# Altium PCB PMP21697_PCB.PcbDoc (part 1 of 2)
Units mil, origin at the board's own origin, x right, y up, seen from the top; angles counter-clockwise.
Board outline 4950 x 3450 mil, 6 copper layers (Top Layer, Signal Layer 1, Signal Layer 2, Signal Layer 3, Signal Layer 4, Bottom Layer), stack 60.502 mil thick; 163 components, 60 nets, 332 pads, 953 vias.
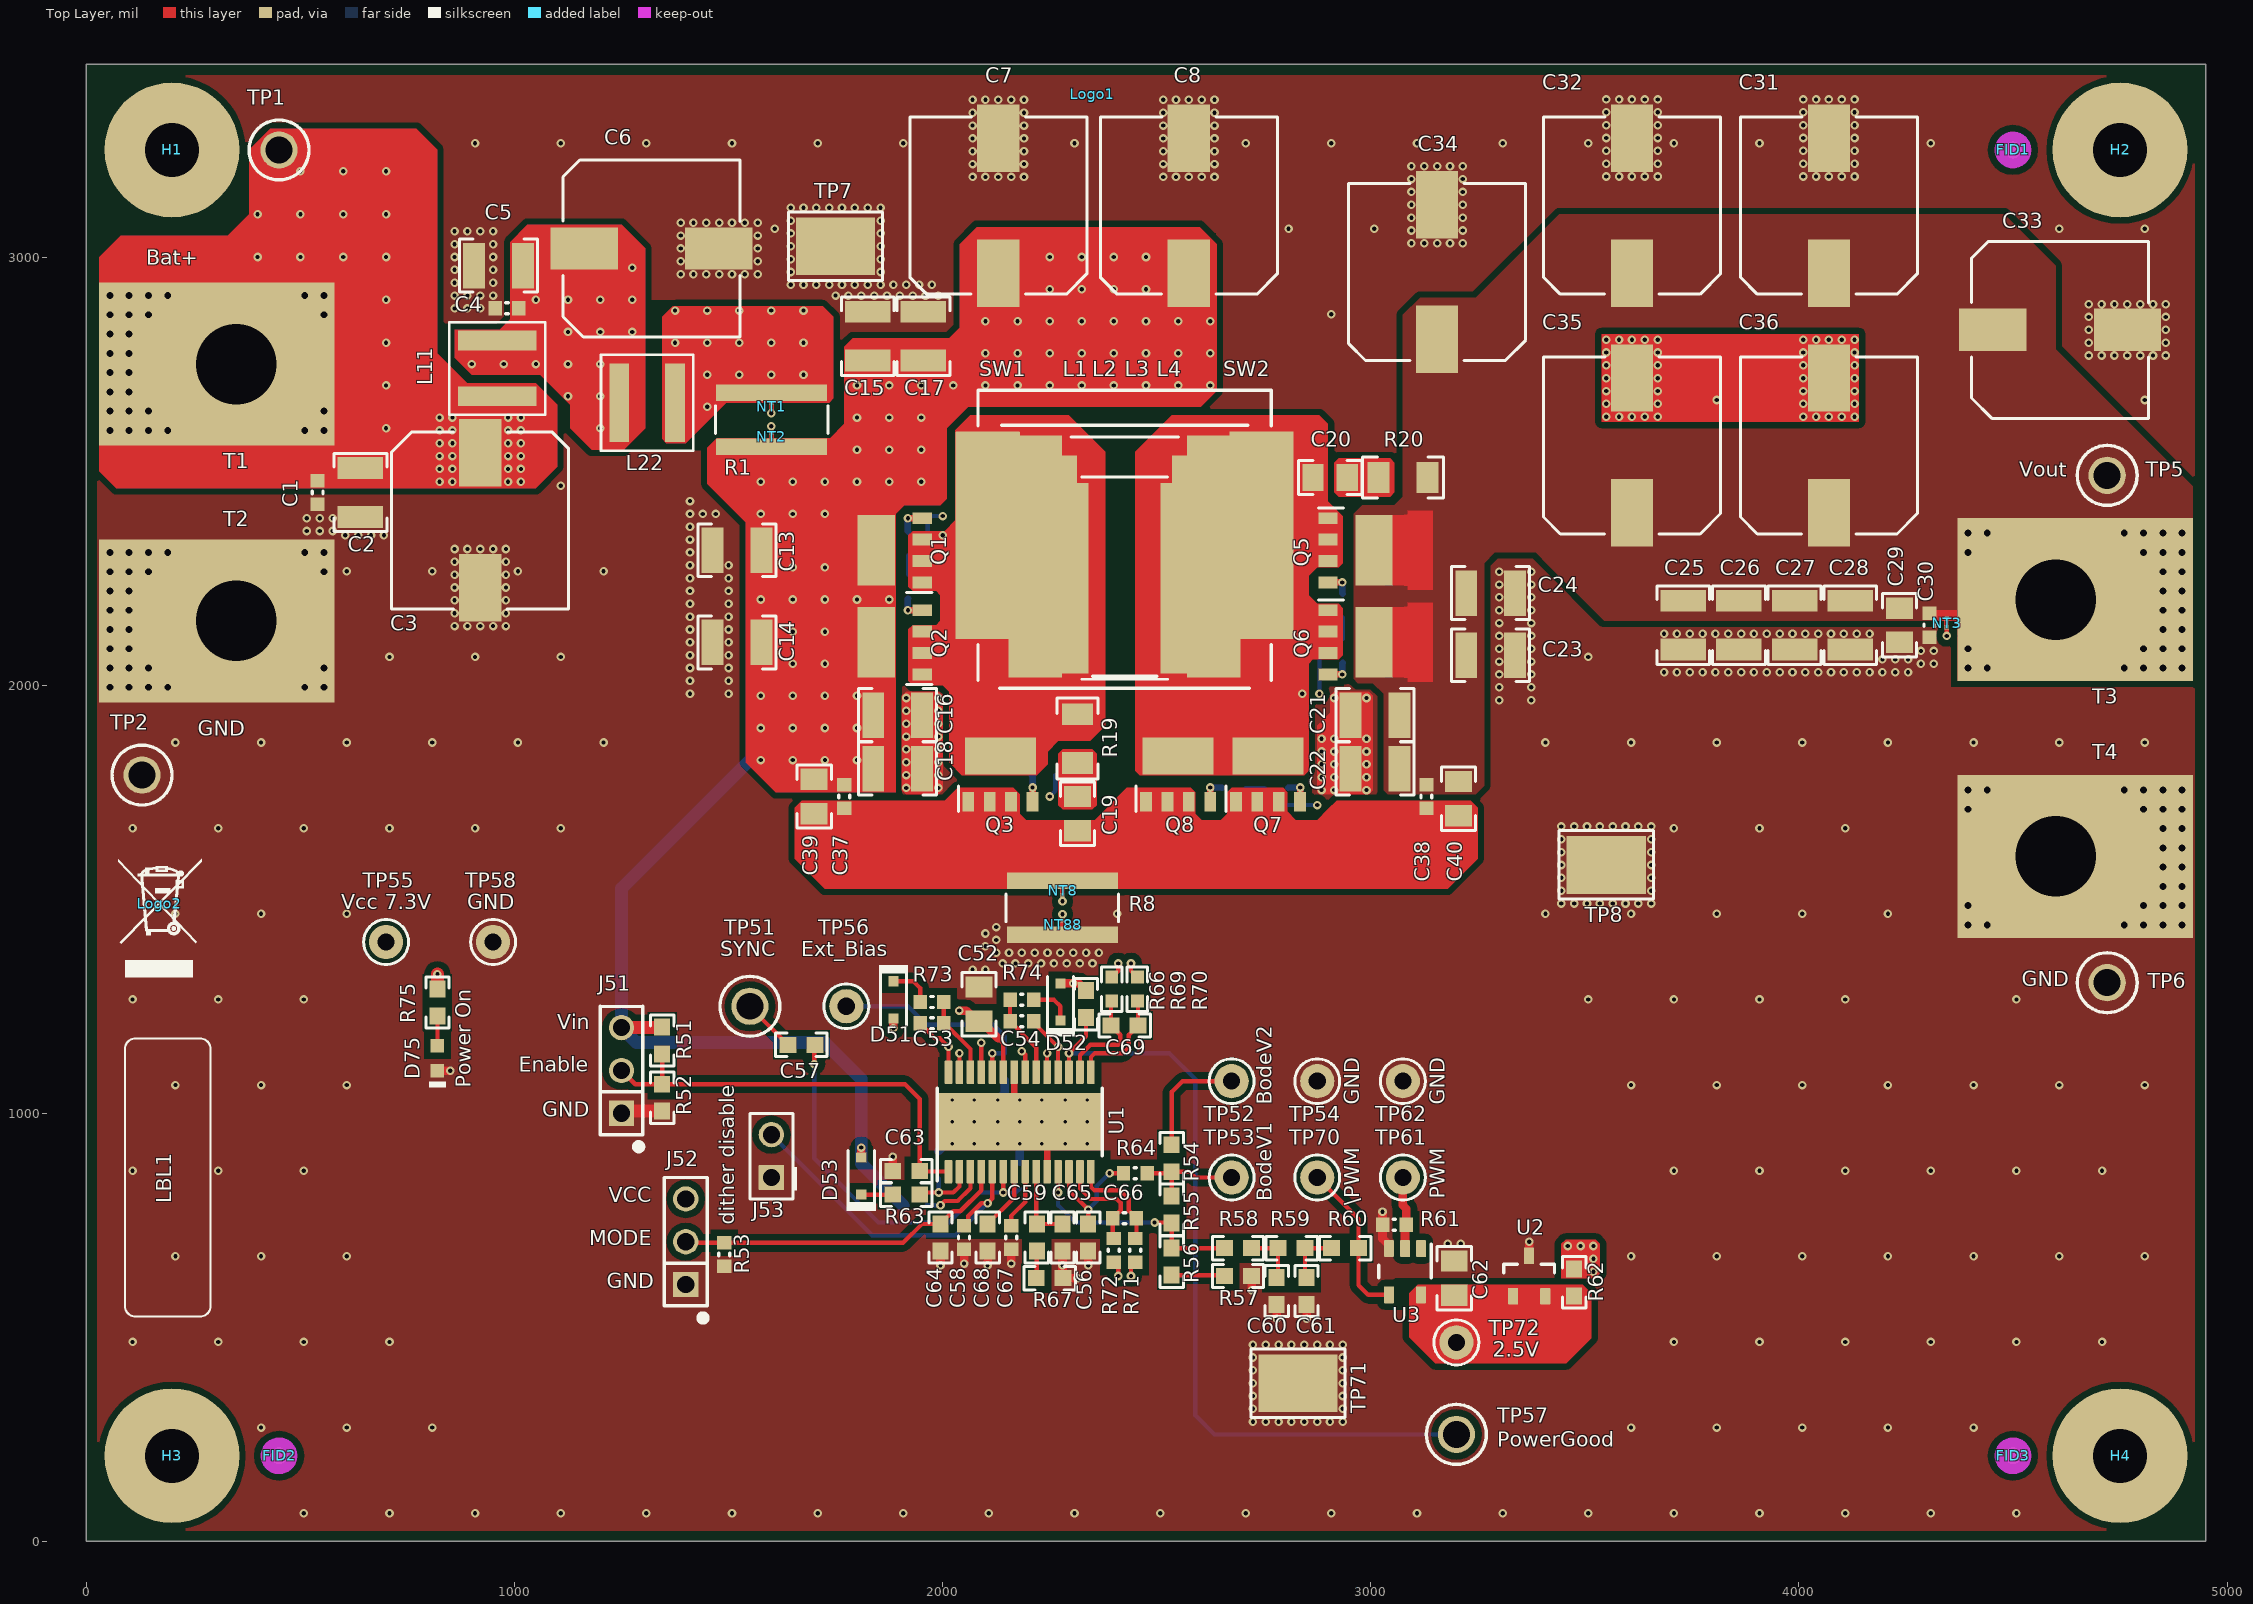
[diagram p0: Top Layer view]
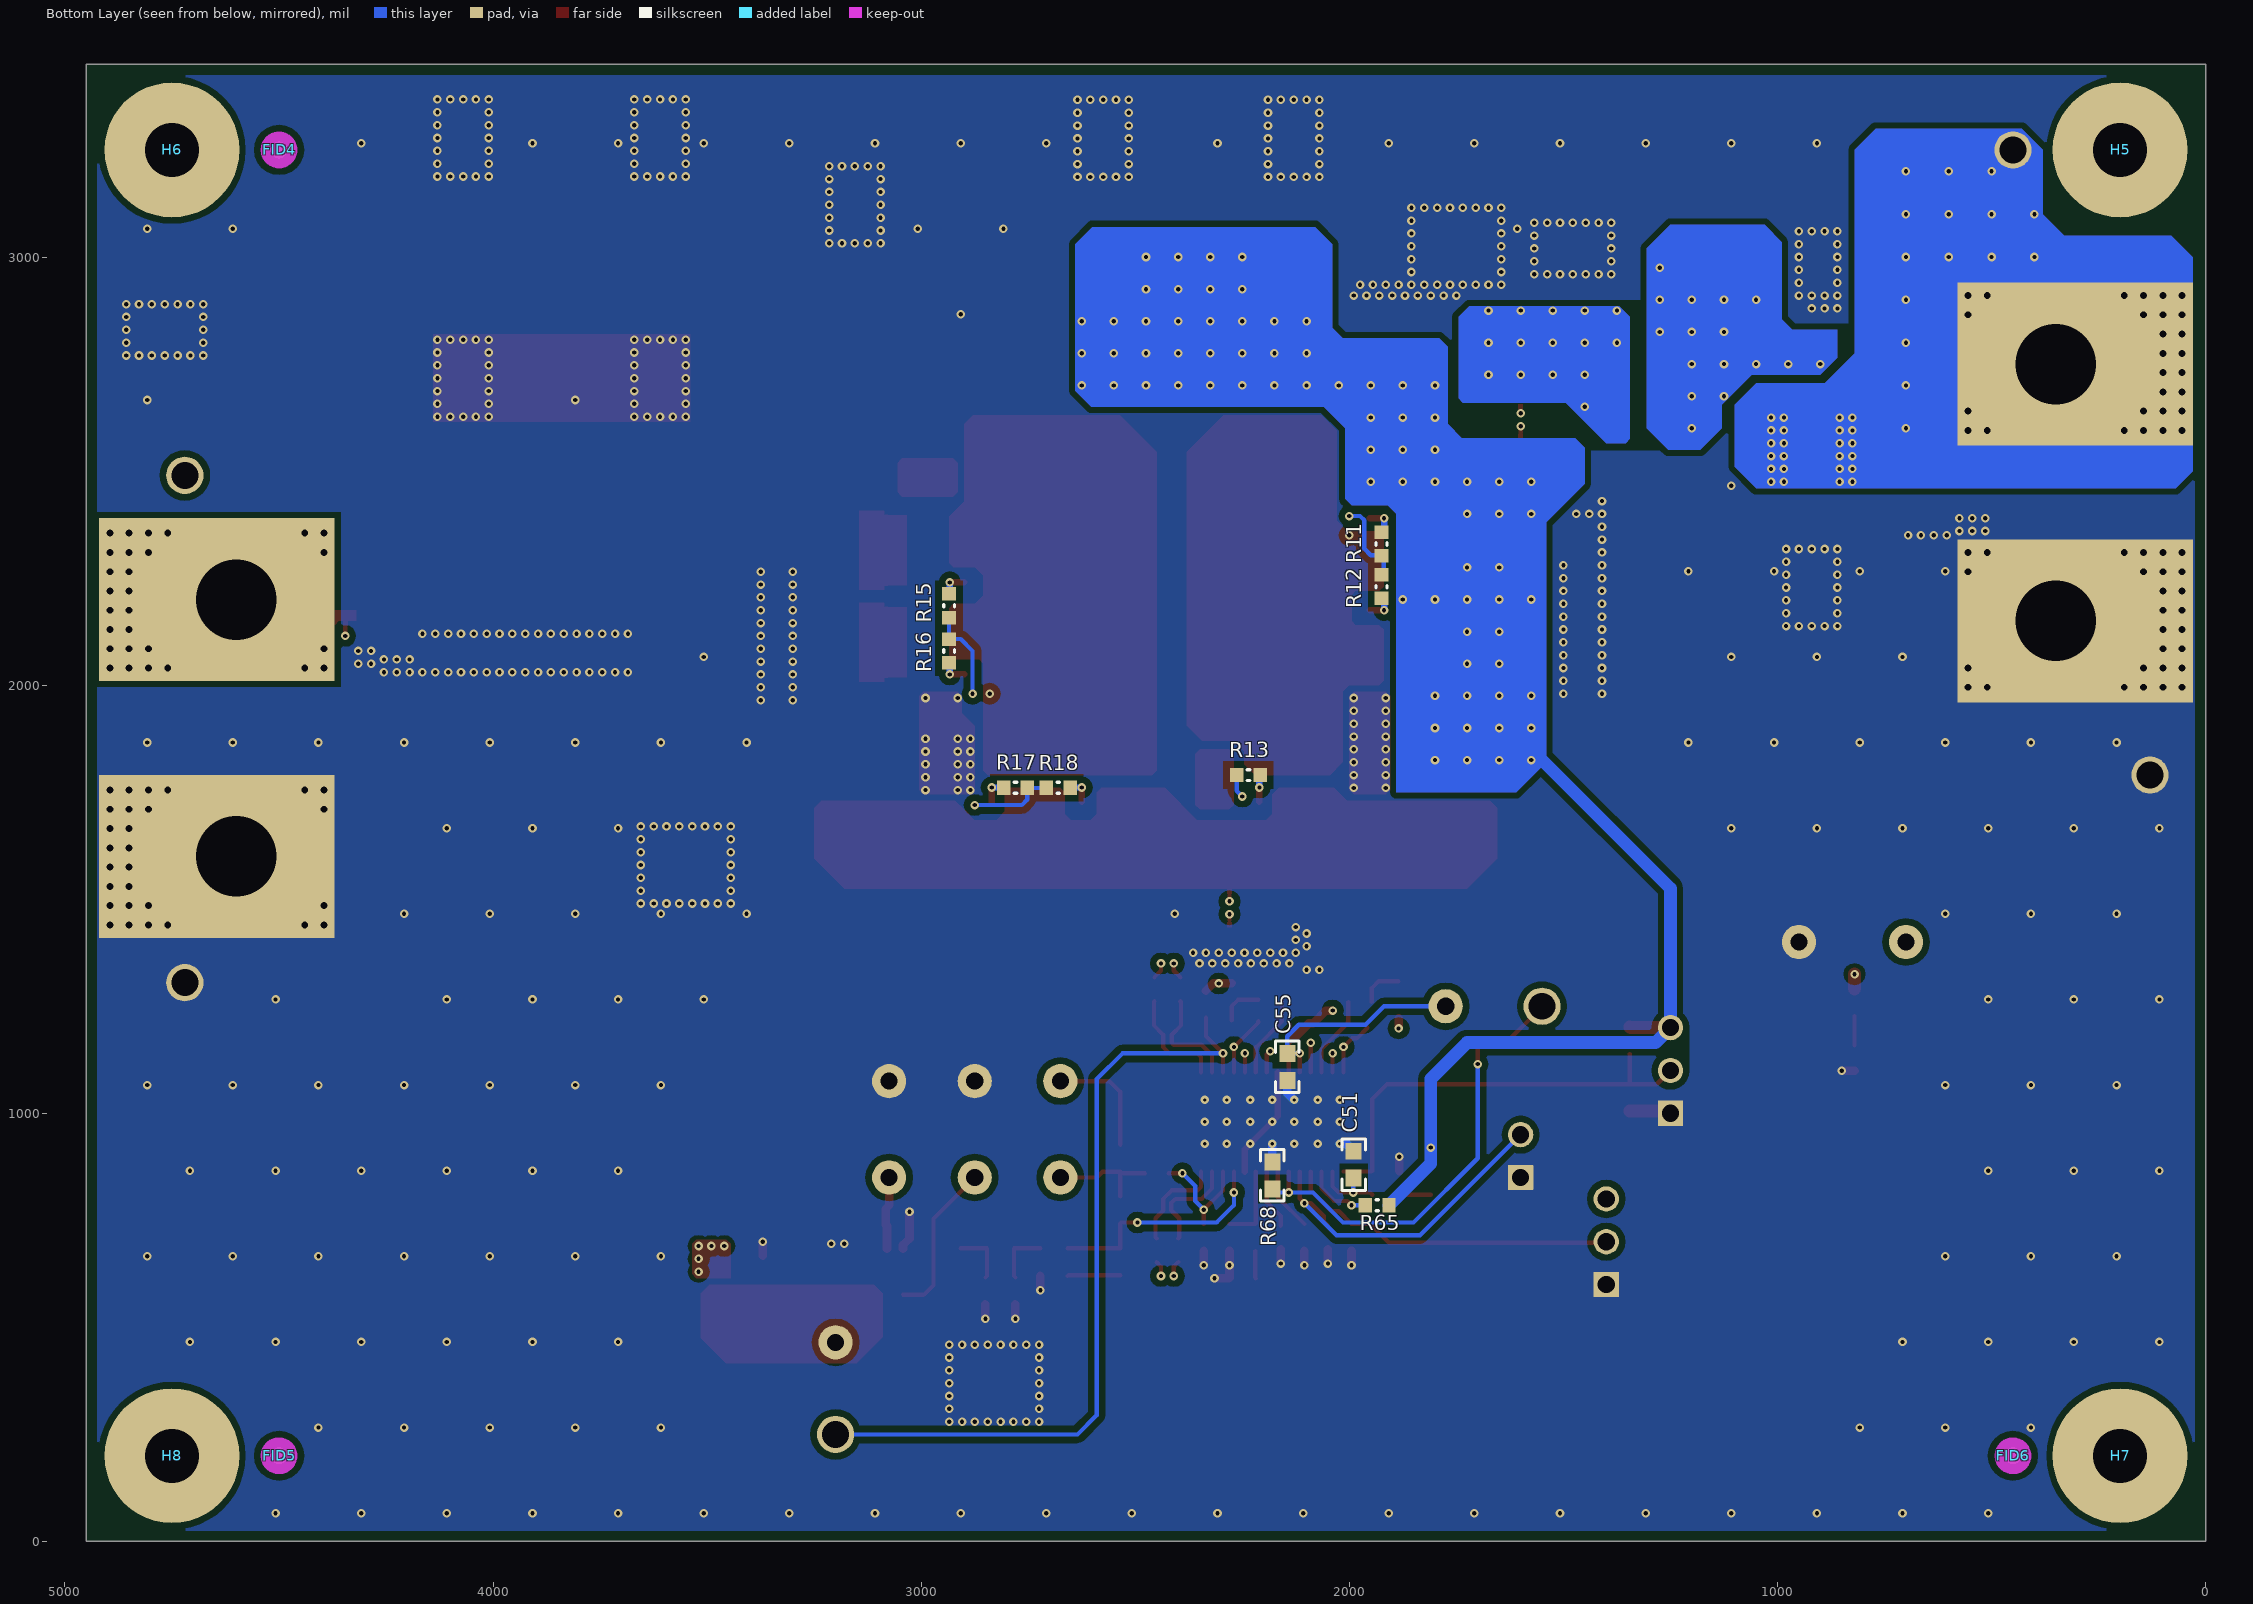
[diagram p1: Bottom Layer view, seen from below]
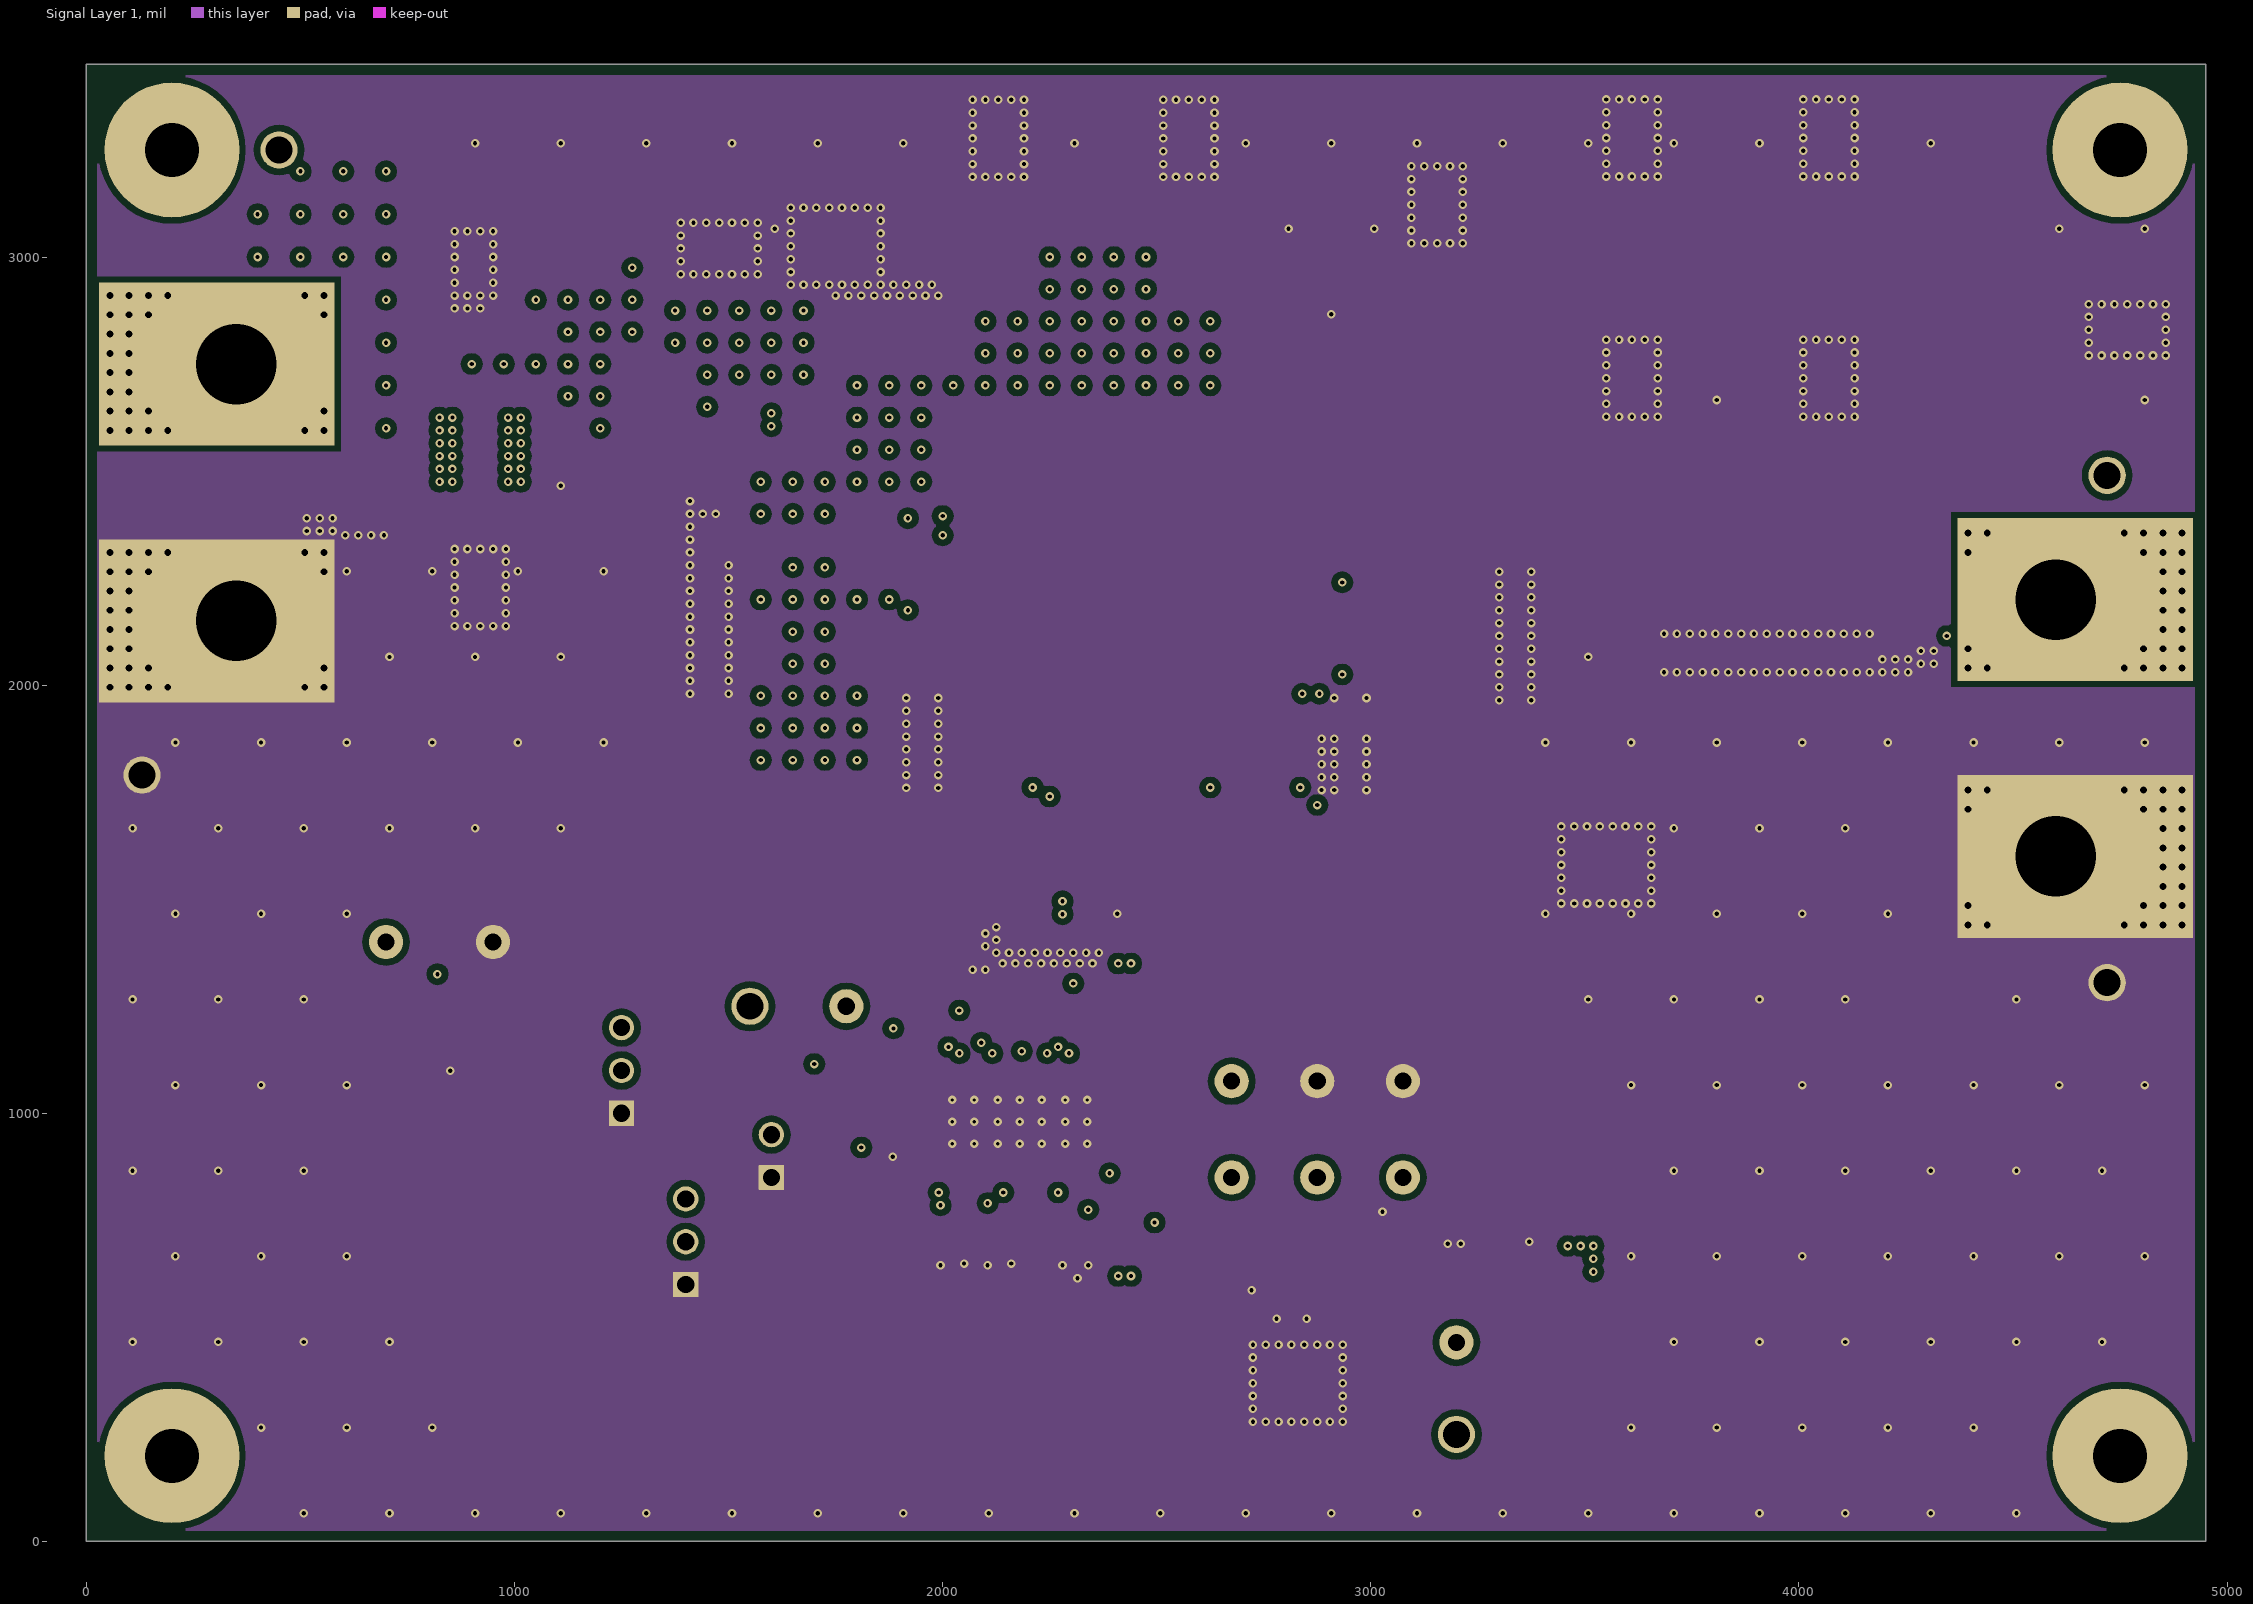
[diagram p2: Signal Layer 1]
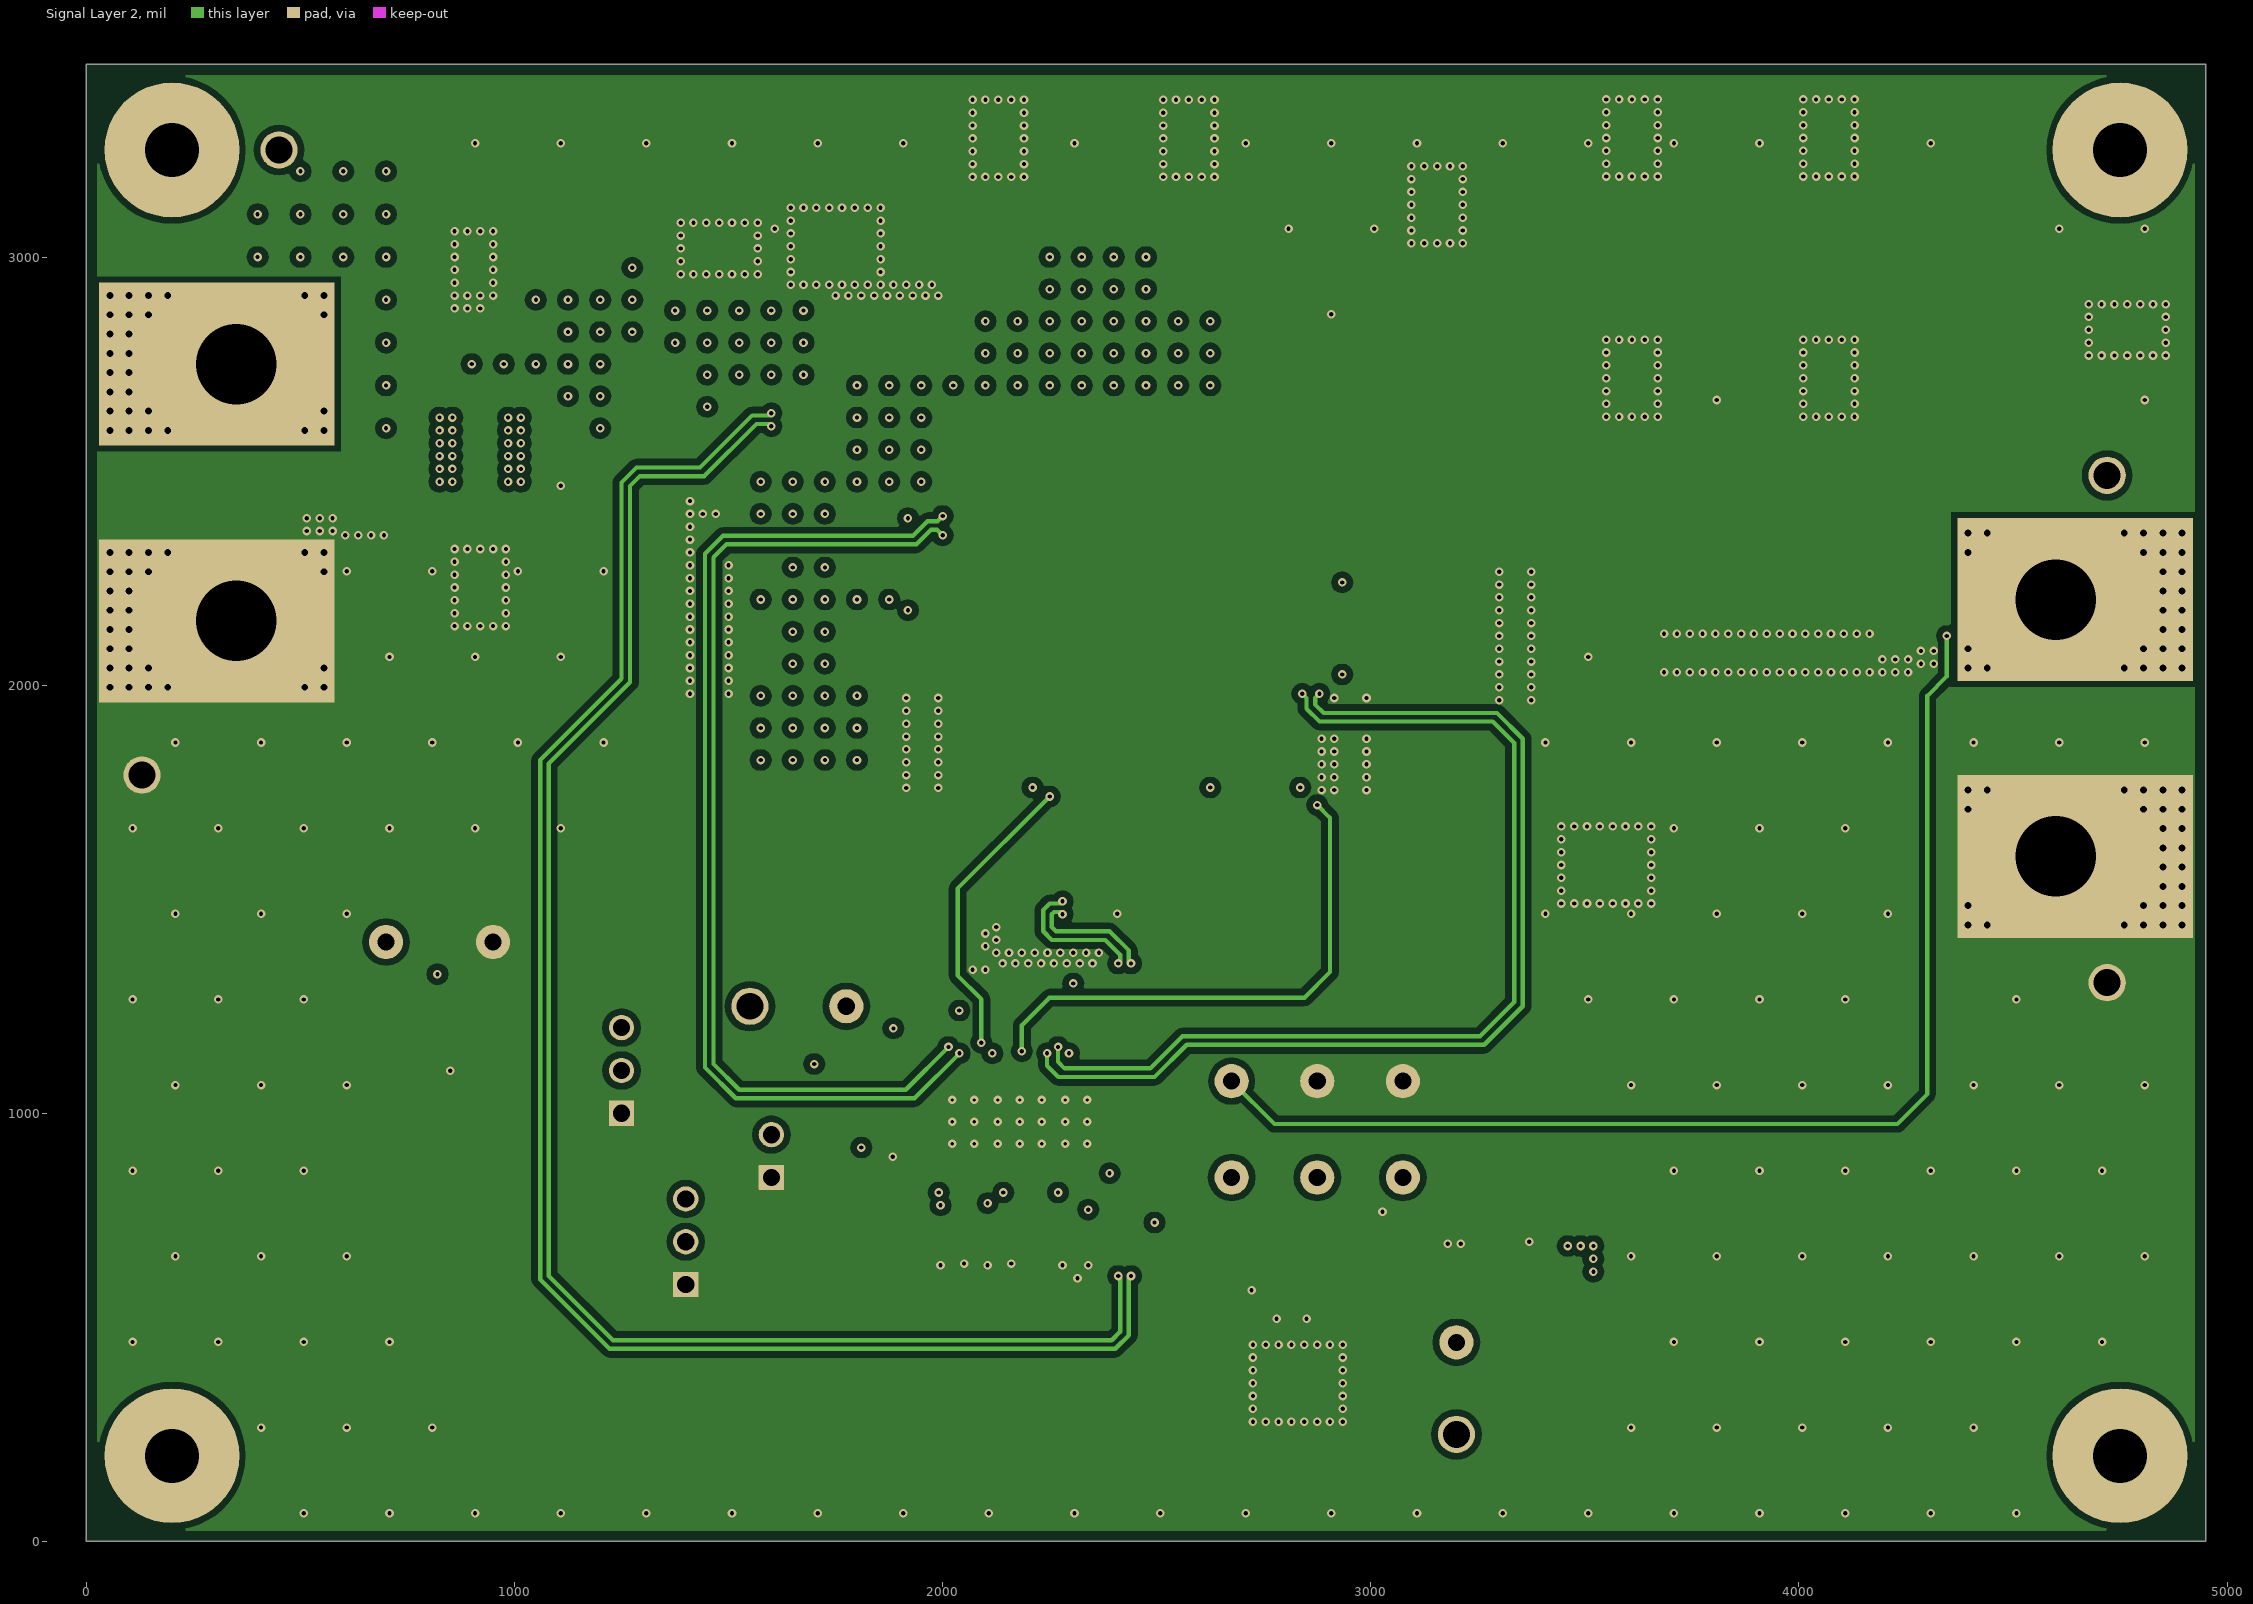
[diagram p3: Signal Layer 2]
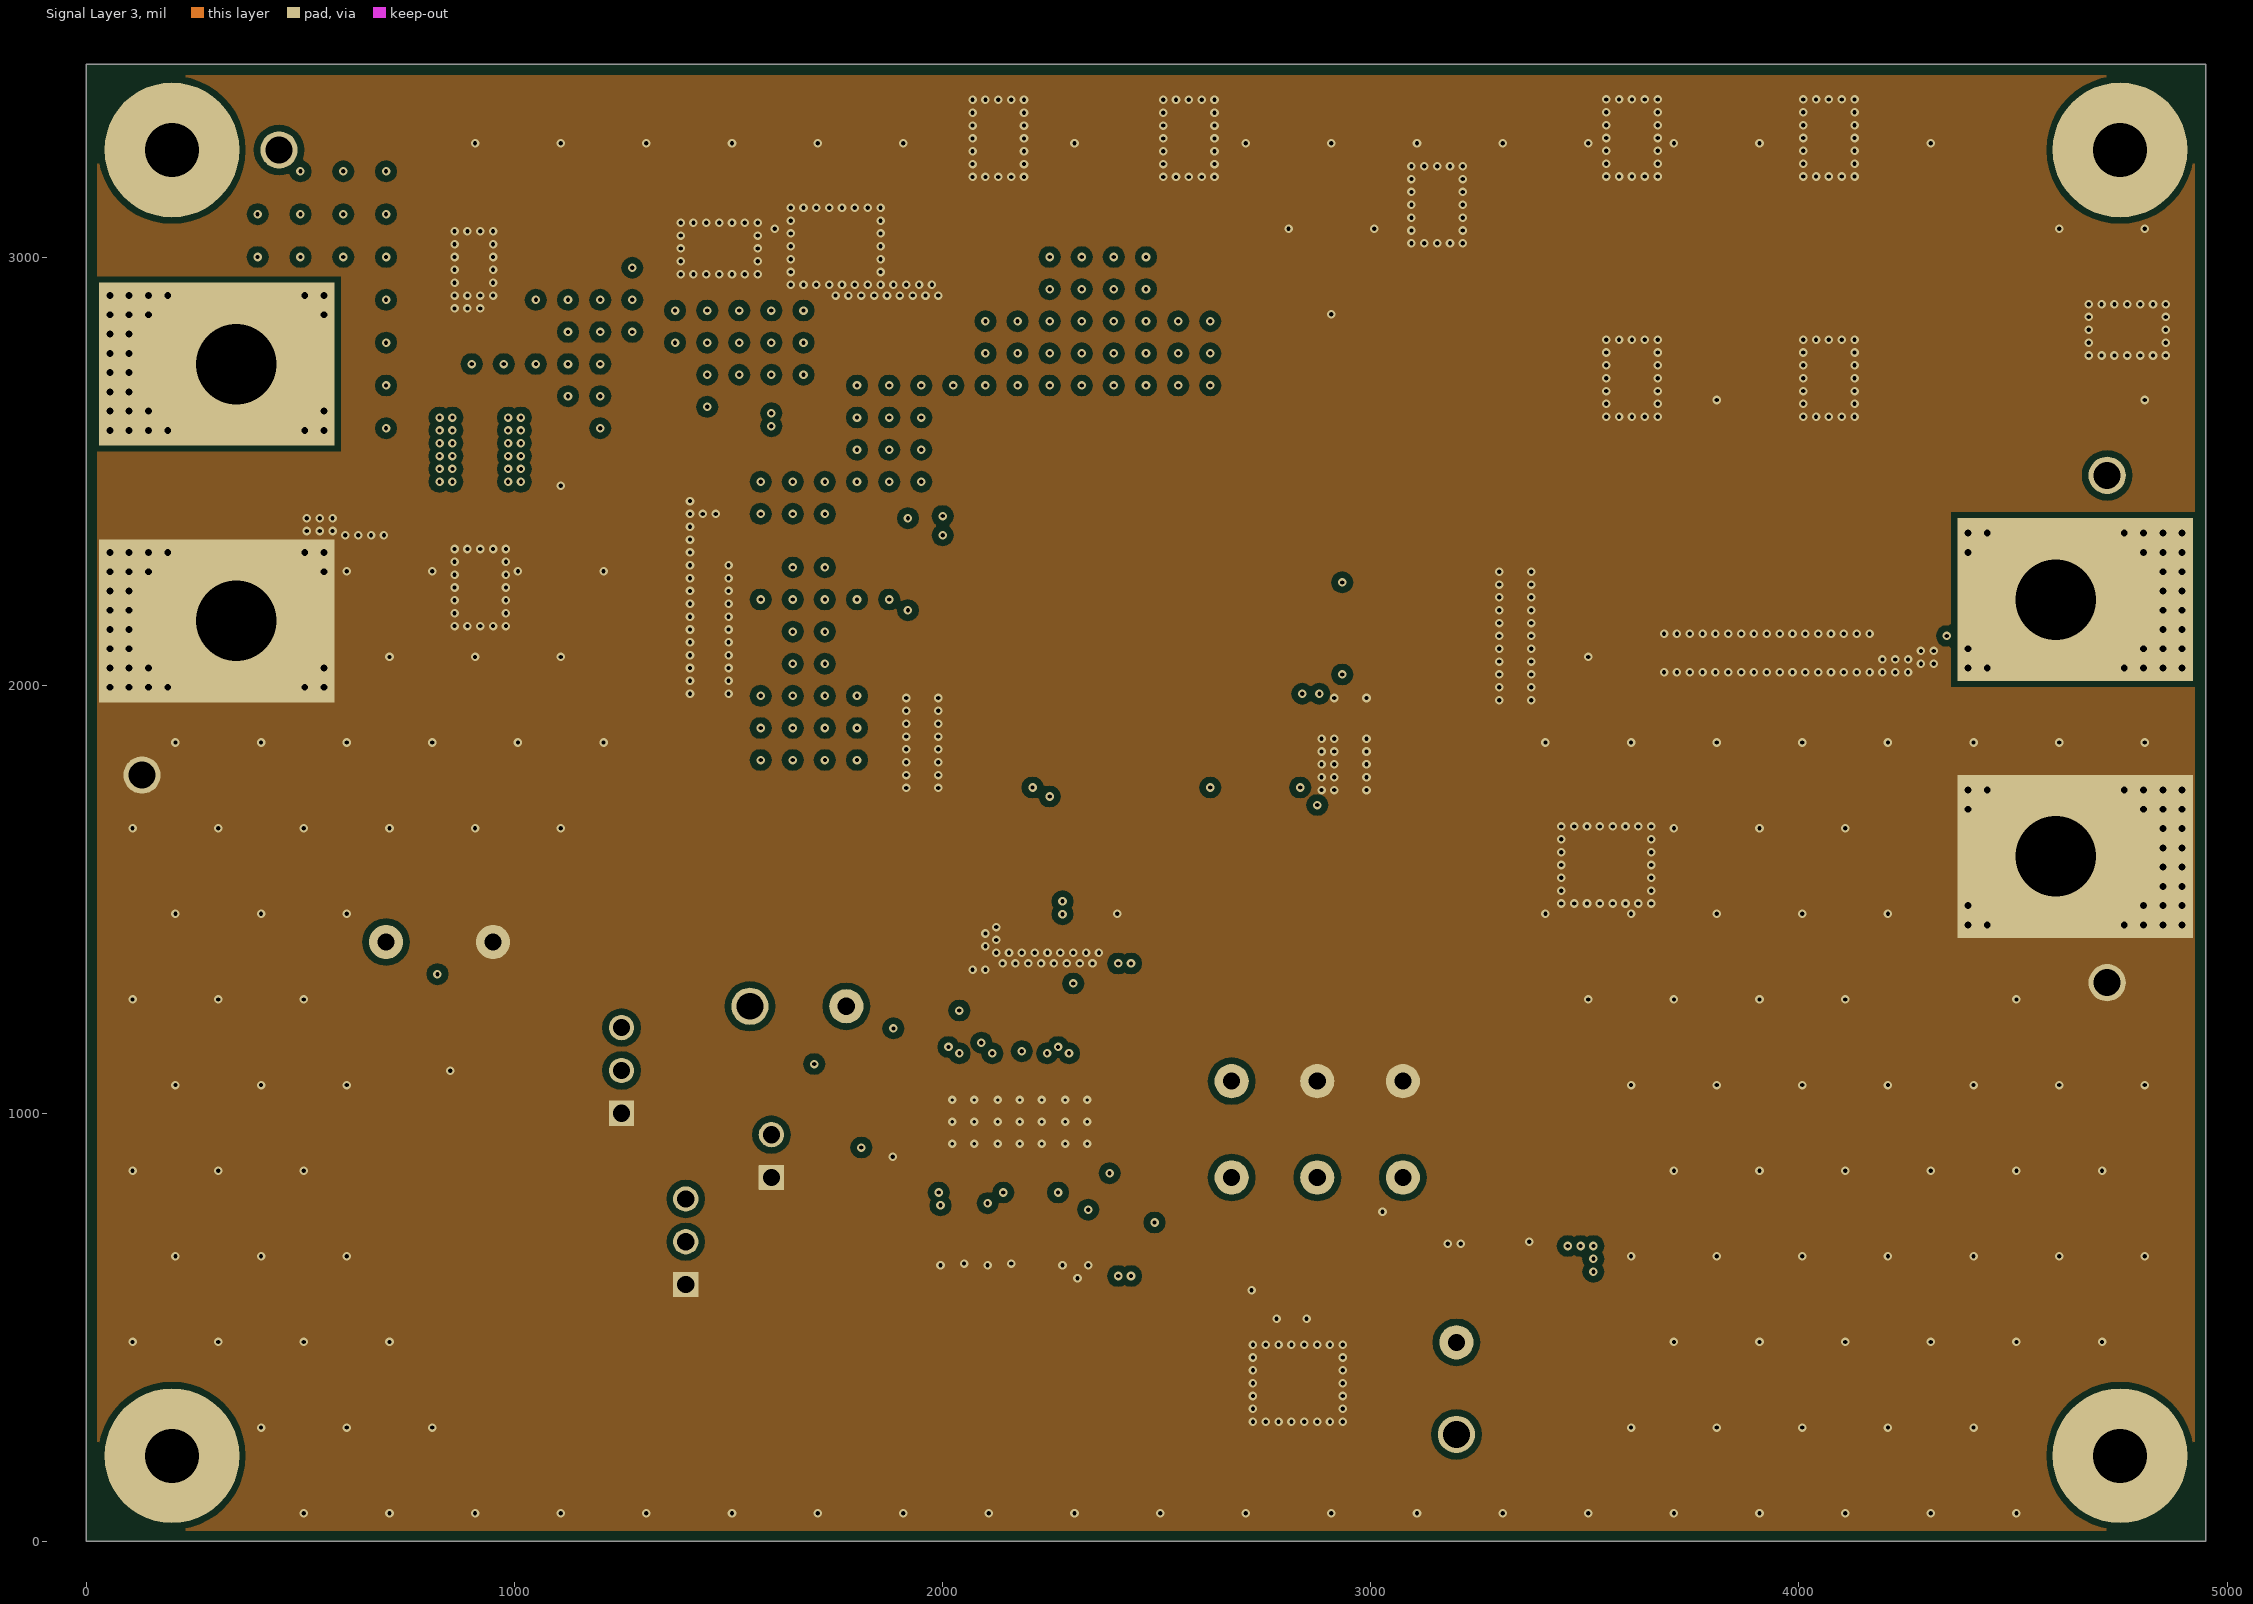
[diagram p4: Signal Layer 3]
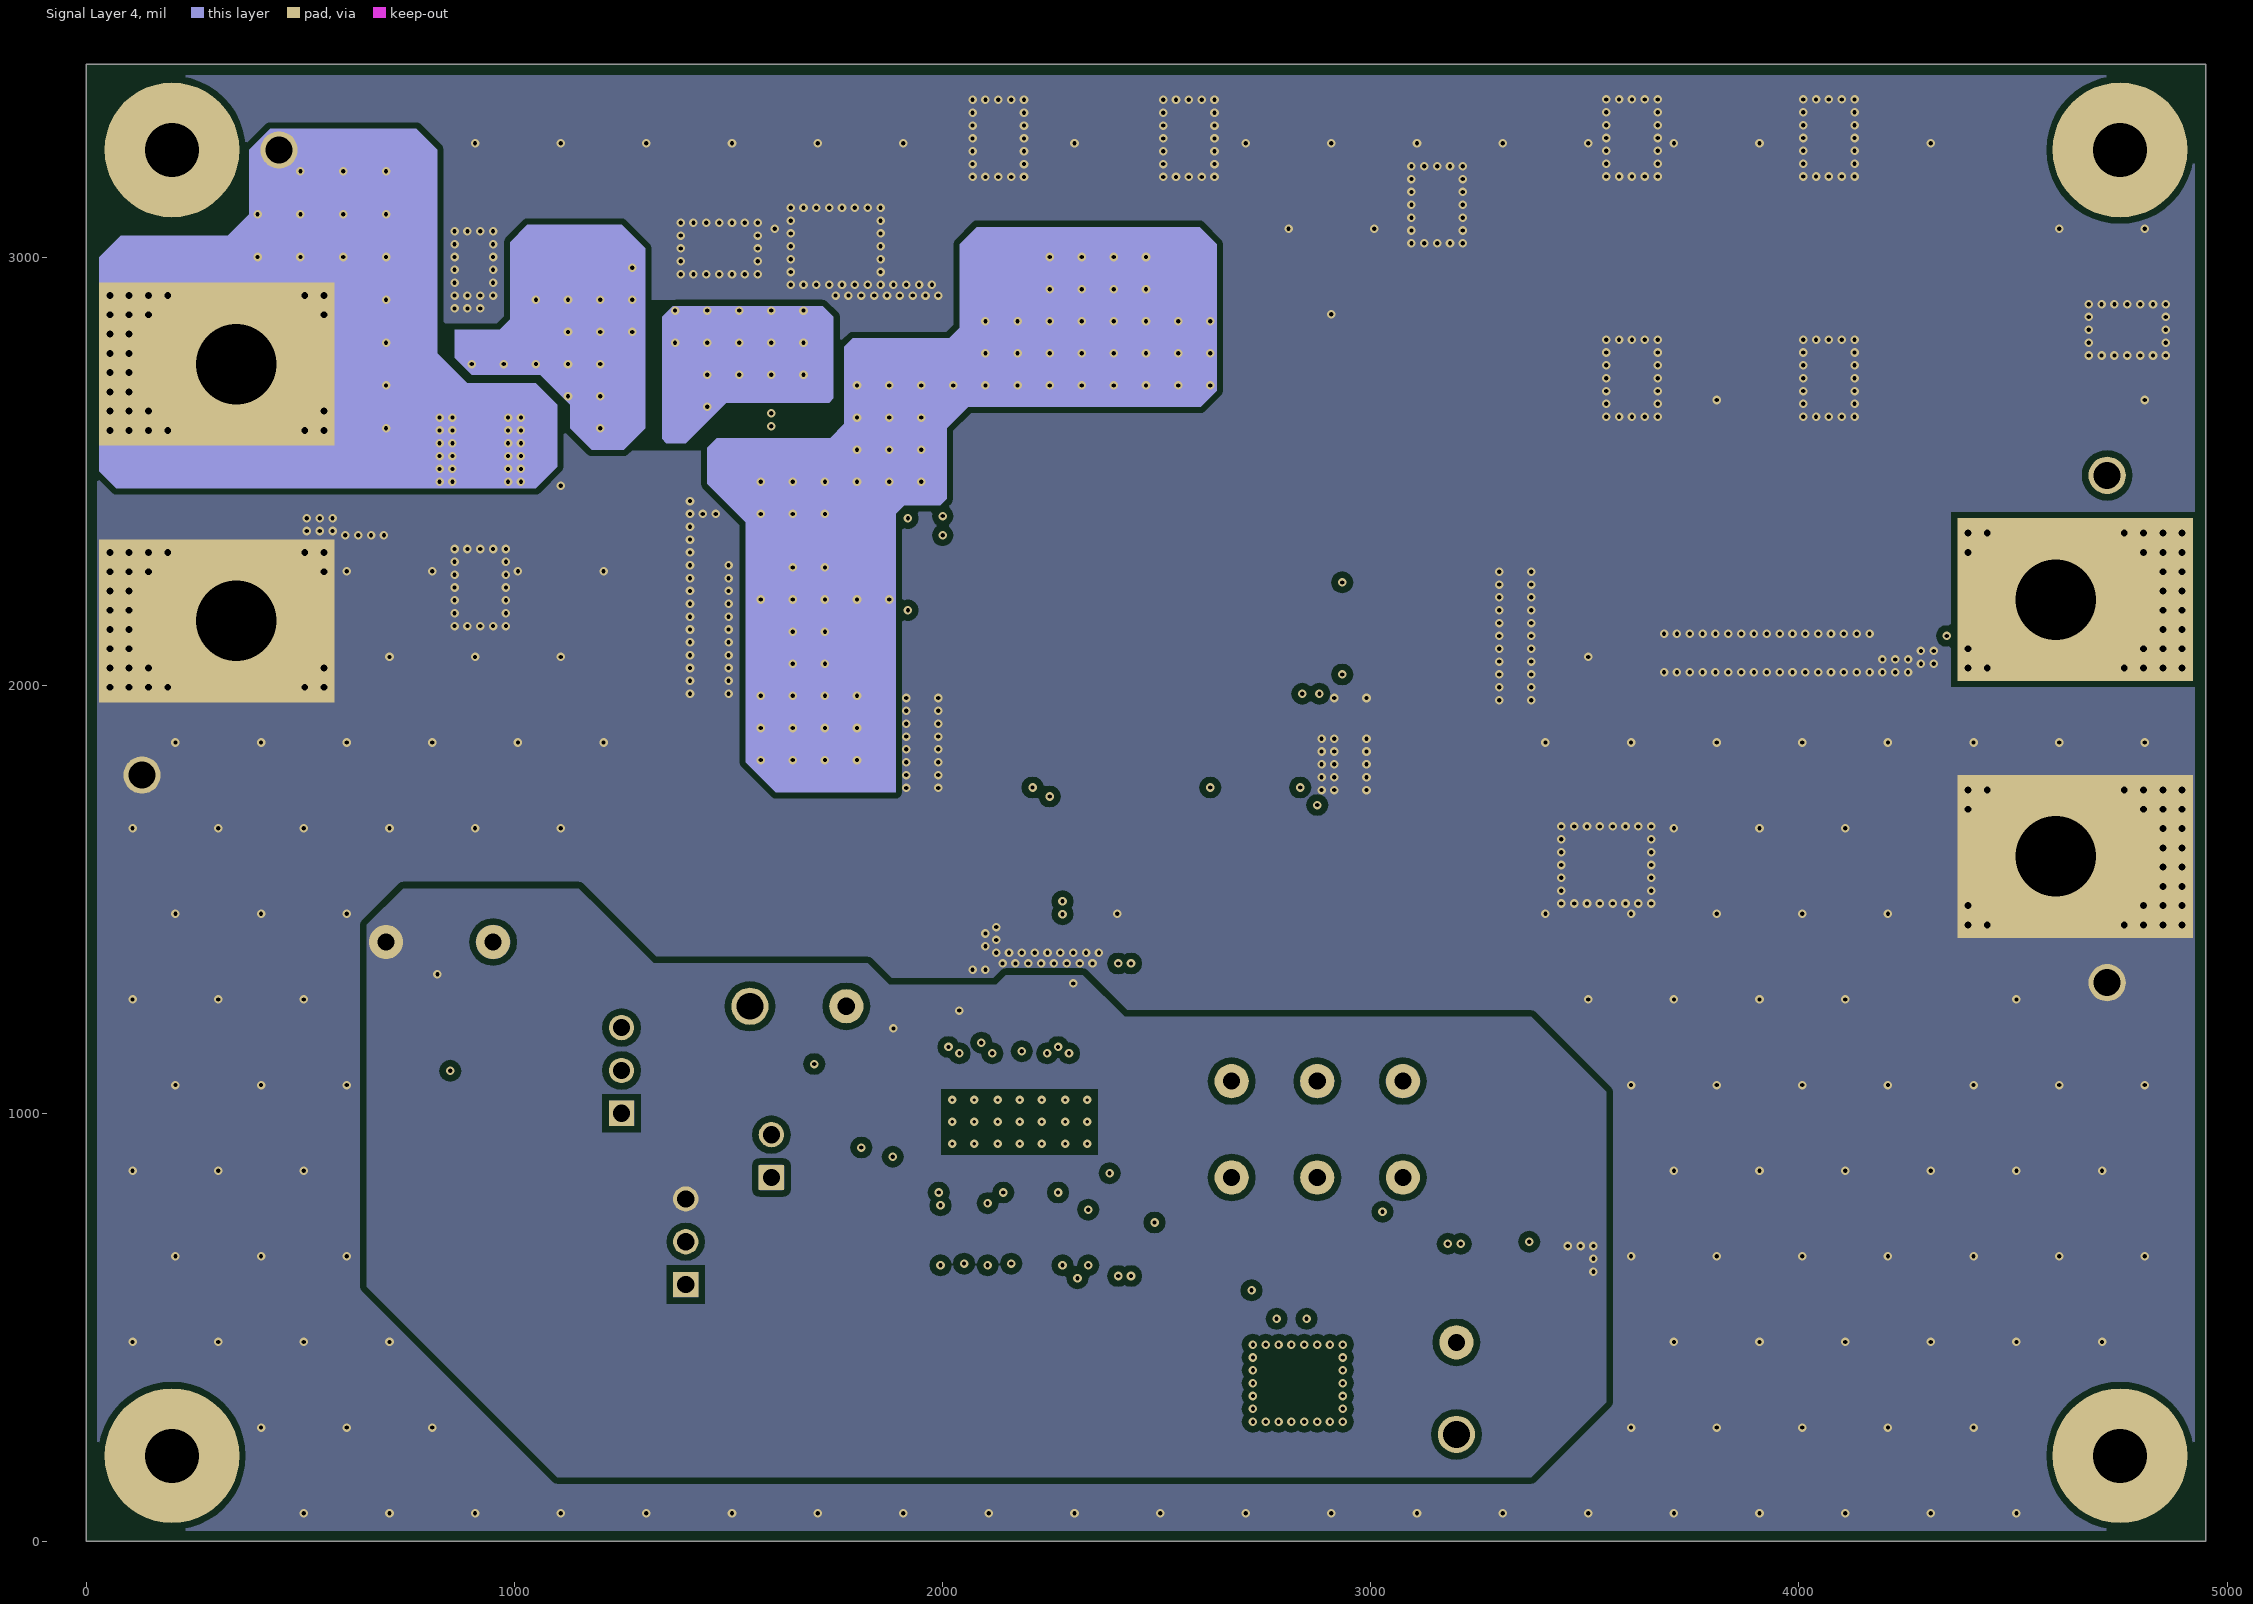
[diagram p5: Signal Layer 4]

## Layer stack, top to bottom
Top Solder: solder mask 0.4, Solder Resist, Dk 3.5
Top Layer: signal copper 1.417
Dielectric1: prepreg 7, FR-4, Dk 4.2
Signal Layer 1: signal copper 1.417
Dielectric 2: core 6, FR-4, Dk 4.2
Signal Layer 2: signal copper 1.417
Dielectric 3: prepreg 26, FR-4, Dk 4.2
Signal Layer 3: signal copper 1.417
Dielectric 4: core 6, FR-4, Dk 4.2
Signal Layer 4: signal copper 1.417
Dielectric 5: prepreg 7, FR-4, Dk 4.2
Bottom Layer: signal copper 1.417
Bottom Solder: solder mask 0.4, Solder Resist, Dk 3.5

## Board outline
0,0 4950,0 4950,3450 0,3450

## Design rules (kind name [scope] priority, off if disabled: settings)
AcuteAngle [All] p1: minimum=4.50000000000000E+0001 checktracksonly=FALSE
AssemblyTestPointUsage [All] p1: valid=2
BoardOutlineClearance BoardOutlineClearance_MountingHoles [OnCopper and InComponentClass('Mounting Holes')] p1: gap=40 ignorepadtopadclearanceinfootprint=FALSE
BoardOutlineClearance BoardOutlineClearance_Poly [OnCopper and IsPoly] p2: gap=25 ignorepadtopadclearanceinfootprint=FALSE
BoardOutlineClearance [OnCopper and Not InComponentClass('Logo') and not InComponentClass('FiducialMark') and not InRegion(1000,500,4000,800) and not InPoly] p3: gap=20 ignorepadtopadclearanceinfootprint=FALSE
Clearance Clearance_Keepouts [((IsTrack Or IsArc) And Not InPoly) And IsFree and IsKeepOut vs ((IsTrack Or IsArc) And Not InPoly) And IsFree and IsKeepOut] p1: gap=0 ignorepadtopadclearanceinfootprint=FALSE
Clearance Clearance_Poly [InPolygon] p2: gap=15 ignorepadtopadclearanceinfootprint=FALSE except(0: Arc-Hole Track-Hole SMDPad-Hole THPad-Hole Via-Hole Fill-Hole Poly-Hole Region-Hole Text-Hole)
Clearance Clearance_FiducialMark [IsKeepOut and InComponentClass('FiducialMark') vs IsPad and InComponentClass('FiducialMark')] p3: gap=0 ignorepadtopadclearanceinfootprint=FALSE
Clearance [All] p4: gap=7.87 ignorepadtopadclearanceinfootprint=FALSE except(0: Arc-Hole Track-Hole SMDPad-Hole THPad-Hole Via-Hole Fill-Hole Poly-Hole Region-Hole Text-Hole)
ComponentClearance Net-tie [HasFootprint('Net-Tie_10mil')] p1: gap=0 collisioncheckmode=3 verticalgap=0 showdistances=FALSE
ComponentClearance "Dual Footprints" [InComponent('L1') or InComponent('L2') or InComponent('L3') or InComponent('L4') vs InComponent('L1') or InComponent('L2') or InComponent('L3') or InComponent('L4')] p2: gap=0 collisioncheckmode=3 verticalgap=0 showdistances=FALSE
ComponentClearance ComponentClearance_MountingHoles_FiducialMarks [InComponentClass('Mounting Holes') vs InComponentClass('FiducialMark')] p3: gap=50 collisioncheckmode=3 verticalgap=10 showdistances=FALSE
ComponentClearance ComponentClearance_Shunt [InComponentClass('Header') vs InComponentClass('Shunt')] p4: gap=0 collisioncheckmode=3 verticalgap=0 showdistances=FALSE
ComponentClearance ComponentClearance_Logo [InComponentClass('Logo')] p5: gap=50 collisioncheckmode=3 verticalgap=10 showdistances=FALSE
ComponentClearance ComponentClearance_ScrewToNut [(HasFootprint('NY PMS 440 0025 PH')) vs (HasFootprint('Keystone_1902C'))] p6: gap=5 collisioncheckmode=3 verticalgap=10 showdistances=FALSE
ComponentClearance ComponentClearance_MountingHoles [InComponentClass('Mounting Holes')] p7: gap=50 collisioncheckmode=3 verticalgap=100000 showdistances=FALSE
ComponentClearance ComponentClearance_SmallPassives [HasFootprint('0201*') or HasFootprint('0402*') or HasFootprint('0508') or HasFootprint('0603*') or HasFootprint('0612') or HasFootprint('0805*') or HasFootprint('0815*') or HasFootprint('0830*') or HasFootprint('1206*') or HasFootprint('1210*') or HasFootprint('1808*') or HasFootprint('1812*') or HasFootprint('1825*') or HasFootprint('2010*') or HasFootprint('2220*') or HasFootprint('2225*') or HasFootprint('2512*') or HasFootprint('2728*') or HasFootprint('3518*') vs HasFootprint('0201*') or HasFootprint('0402*') or HasFootprint('0508') or HasFootprint('0603*') or HasFootprint('0612') or HasFootprint('0805*') or HasFootprint('0815*') or HasFootprint('0830*') or HasFootprint('1206*') or HasFootprint('1210*') or HasFootprint('1808*') or HasFootprint('1812*') or HasFootprint('1825*') or HasFootprint('2010*') or HasFootprint('2220*') or HasFootprint('2225*') or HasFootprint('2512*') or HasFootprint('2728*') or HasFootprint('3518*')] p8: gap=10 collisioncheckmode=3 verticalgap=10 showdistances=FALSE
ComponentClearance ComponentClearance_THtoSMT [IsThruComponent vs IsSMTComponent] p9: gap=10 collisioncheckmode=3 verticalgap=30 showdistances=FALSE
ComponentClearance ComponentClearance_THtoTH [IsThruComponent vs IsThruComponent] p10: gap=30 collisioncheckmode=3 verticalgap=30 showdistances=FALSE
ComponentClearance [All] p11: gap=10 collisioncheckmode=3 verticalgap=10 showdistances=FALSE
DiffPairsRouting [All] p1: maxlimit=100 minlimit=10 mostfreqgap=10 toplayer_minwidth=15 toplayer_maxwidth=15 toplayer_prefwidth=15 midlayer1_minwidth=15 midlayer1_maxwidth=15 midlayer1_prefwidth=15 midlayer2_minwidth=15 midlayer2_maxwidth=15 midlayer2_prefwidth=15 midlayer3_minwidth=15 midlayer3_maxwidth=15 midlayer3_prefwidth=15 midlayer4_minwidth=15 midlayer4_maxwidth=15 midlayer4_prefwidth=15 bottomlayer_minwidth=15 bottomlayer_maxwidth=15 bottomlayer_prefwidth=15 maxuncoupledlength=1000
FabricationTestPointUsage TestPointUsage [All] p1: valid=2 allowmultiple=FALSE
FabricationTestpoint Testpoint [All] p1: side=3 testpointundercomponent=TRUE minsize=40 maxsize=100 preferedsize=60 minholesize=0 maxholesize=40 preferedholesize=32 testpointgrid=1 allowsidetop=TRUE allowsidebottom=TRUE usegrid=TRUE gridtolerance=0.01
FanoutControl Fanout_LCC [IsLCC] p1: bgadir=Out bgaviamode=Centered fanoutstyle=Auto fanoutdirection=Alternating viagrid=1 // Fanout_LCC (Default Rule)
FanoutControl Fanout_BGA [IsBGA] p2: bgadir=Out bgaviamode=Centered fanoutstyle=Auto fanoutdirection=Alternating viagrid=1 // Fanout_BGA (Default Rule)
FanoutControl Fanout_Default [All] p4: bgadir=Out bgaviamode=Centered fanoutstyle=Auto fanoutdirection=Alternating viagrid=1 // Fanout_Default (Default Rule)
FanoutControl Fanout_Small [(CompPinCount < 5)] p5: bgadir=Out bgaviamode=Centered fanoutstyle=Auto fanoutdirection=OutThenIn viagrid=1 // Fanout_Small (Default Rule)
HoleSize [All] p1: absolutevalues=TRUE maxlimit=251 minlimit=7.87 maxpercent=80.000 minpercent=20.000
MinimumAnnularRing MinimumAnnularRing_ThermalPadVias [IsVia and InAnyComponent] p1: minimumring=5.91
MinimumAnnularRing [All] p2: minimumring=5
MinimumSolderMaskSliver MinimumSolderMaskSliver_Logo [InComponentClass('Logo') vs InComponentClass('Logo')] p1: minsoldermaskwidth=0.7
MinimumSolderMaskSliver [All] p2: minsoldermaskwidth=3.94
PlaneConnect [All] p1: planeconnectstyle=Relief reliefexpansion=10 reliefentries=4 reliefconductorwidth=10 reliefairgap=10
PolygonConnect [All] p1: connectstyle=Direct reliefconductorwidth=10 reliefentries=4 polygonreliefangle="90 Angle" airgapwidth=10
RoutingVias ThermalPadVias [IsVia and InAnyComponent] p1: holewidth=7.87 width=19.68 viastyle="Through Hole" minholewidth=7.87 minwidth=19.68 maxholewidth=16 maxwidth=40
RoutingVias [All] p2: holewidth=16 width=34 viastyle="Through Hole" minholewidth=7.87 minwidth=16 maxholewidth=40 maxwidth=65
SilkToBoardRegionClearance [Not ((IsComment or IsDesignator) And (Hide <> 'False')) and not InRegion(1000,500,4000,800)] p1:
SilkToSilkClearance SilkToSilkClearance_Pb-FreeLogo [(HasFootprint('Pb-Free_Overlay_Medium') OR HasFootprint('Pb-Free_Overlay_Small')) vs (HasFootprint('Pb-Free_Overlay_Medium') OR HasFootprint('Pb-Free_Overlay_Small'))] p1: silktosilkclearance=0
SilkToSilkClearance [All] p2: silktosilkclearance=4
SilkToSolderMaskClearance SilkToComponentPadClearance [(IsPad or IsFill or IsRegion) and InAnycomponent] p1: minsilkscreentomaskgap=5 clearancetoexposedcopper=TRUE
SilkToSolderMaskClearance "Silk to Solder Mask Opening" [All] p2: minsilkscreentomaskgap=4 clearancetoexposedcopper=FALSE
SolderMaskExpansion [All] p1: expansion=1.97
Width [All] p1: maxlimit=100 minlimit=6 preferedwidth=10 checkconnectedcopper=TRUE
15 further rules are at their usual default settings.

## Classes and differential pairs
component class Label: LBL1
component class AssemblyNote: ZZ1 ZZ2 ZZ3 ZZ4
component class FiducialMark: FID1 FID2 FID3 FID4 FID5 FID6
component class Hardware: FID1 FID2 FID3 FID4 FID5 FID6 H1 H2 H3 H4 H5 H6 H7 H8 LBL1 Logo1 Logo2 ZZ1 ZZ2 ZZ3 ZZ4
component class "Mounting Holes": H1 H2 H3 H4
component class Header: J51 J52 J53
component class MainLM5176_BB_35Vmax8A: C1 C2 C3 C4 C5 C6 C7 C8 C13 C14 C15 C16 C17 C18 C19 C20 C21 C22 C23 C24 C25 C26 C27 C28 C29 C30 C31 C32 C33 C34 C35 C36 C37 C38 C39 C40 C51 C52 C53 C54 C55 C56 C57 C58 C59 C60 C61 C62 C63 C64 C65 C66 C67 C68 C69 D51 D52 D53 D75 J51 J52 J53 L1 L2 L3 L4 L11 L22 NT1 NT2 NT3 NT8 NT88 Q1 Q2 Q3 Q5 Q6 Q7 Q8 R1 R8 R11 R12 R13 R15 R16 R17 R18 R19 R20 R51 R52 R53 R54 R55 R56 R57 R58 R59 R60 R61 R62 R63 R64 R65 R66 R67 R68 R69 R70 R71 R72 R73 R74 R75 T1 T2 T3 T4 TP1 TP2 TP5 TP6 TP7 TP8 TP51 TP52 TP53 TP54 TP55 TP56 TP57 TP58 TP61 TP62 TP70 TP71 TP72 U1 U2 U3

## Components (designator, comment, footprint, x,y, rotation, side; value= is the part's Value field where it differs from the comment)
C1 "Capacitor" 0603L 540,2450 r270 top
C2 "Capacitor" 1210_270 640,2450 r270 top
C3 "Cap_Polarized" SM_RADIAL_10BMM 920,2385 r270 top
C4 "Capacitor" 0603L 982.76,2880 r180 top
C5 "Capacitor" 1210_270 962.76,2980 r180 top
C6 "Cap_Polarized" SM_RADIAL_10BMM 1320,3020 r0 top
C7 "Cap_Polarized" SM_RADIAL_10BMM 2130,3120 r90 top
C8 "Cap_Polarized" SM_RADIAL_10BMM 2575,3120 r90 top
C13 "Capacitor" 1210_270 1520,2315 r180 top
C14 "Capacitor" 1210_270 1520,2100 r180 top
C15 "Capacitor" 1210_270 1825,2815 r90 top
C16 "Capacitor" 1210_270 1895,1930 r0 top
C17 "Capacitor" 1210_270 1955,2815 r90 top
C18 "Capacitor" 1210_270 1895,1805 r0 top
C19 "C0805C102K5RACTU" 0805_HV 2315,1700 r270 top
C20 "C0805C102K5RACTU" 0805_HV 2905,2485 r180 top
C21 "Capacitor" 1210_270 3010,1930 r180 top
C22 "Capacitor" 1210_270 3010,1805 r180 top
C23 "Capacitor" 1210_270 3280,2070 r0 top
C24 "Capacitor" 1210_270 3280,2215 r0 top
C25 "Capacitor" 1210_270 3730,2140 r270 top
C26 "Capacitor" 1210_270 3860,2140 r270 top
C27 "Capacitor" 1210_270 3990,2140 r270 top
C28 "Capacitor" 1210_270 4120,2140 r270 top
C29 "Capacitor" 0805_HV 4235,2140 r270 top
C30 "Capacitor" 0603L 4305,2140 r270 top
C31 "Cap_Polarized" SM_RADIAL_10BMM 4070,3120 r90 top
C32 "Cap_Polarized" SM_RADIAL_10BMM 3610,3120 r90 top
C33 "Cap_Polarized" SM_RADIAL_10BMM 4610,2830 r0 top
C34 "Cap_Polarized" SM_RADIAL_10BMM 3155,2965 r90 top
C35 "Cap_Polarized" SM_RADIAL_10BMM 3610,2560 r90 top
C36 "Cap_Polarized" SM_RADIAL_10BMM 4070,2560 r90 top
C37 "Capacitor" 0603L 1770,1740 r270 top
C38 "Capacitor" 0603L 3130,1740 r270 top
C39 "Capacitor" 0805_HV 1700,1740 r270 top
C40 "Capacitor" 0805_HV 3205,1735 r270 top
C51 "Capacitor" 0603 1990,880 r90 bottom
C52 "Capacitor" 0805_HV 2085,1255 r270 top
C53 "Capacitor" 0603L 1975,1210 r0 top
C54 "Capacitor" 0603L 2185,1215 r0 top
C55 "CGA3E3X7R1H154K080AB" 0603 2145,1108.5 r270 bottom
C56 "Capacitor" 0603 2340,710 r90 top
C57 "Capacitor" 0603 1670,1160 r180 top
C58 "Capacitor" 0603L 2050,710 r270 top
C59 "Capacitor" 0603 2220,710 r270 top
C60 "CGA3E3X7R1H154K080AB" 0603 2780,585 r270 top
C61 "CGA3E3X7R1H154K080AB" 0603 2850,585 r270 top
C62 "GCM21BC71C106KE36L" 0805_HV 3195,615 r90 top
C63 "Capacitor" 0603 1915,865 r0 top
C64 "Capacitor" 0603 1995,710 r90 top
C65 "Capacitor" 0603 2280,710 r270 top
C66 "Capacitor" 0603L 2425,755 r180 top
C67 "Capacitor" 0603L 2160,710 r270 top
C68 "Capacitor" 0603 2105,710 r270 top
C69 "Capacitor" 0603 2425,1205 r0 top
D51 "DIODE" SOD-323 1885,1265 r270 top
D52 "DIODE" SOD-323 2275,1260 r90 top
D53 "DIODE_SCHOTTKY" SOD-323F 1810,853.31 r90 top
D75 "LTST-C190KGKT" LED_LTST-C190_G 820,1128.7 r270 top
FID1 "Fiducial" Fiducial10-20 4500,3250 r0 top
FID2 "Fiducial" Fiducial10-20 450,200 r0 top
FID3 "Fiducial" Fiducial10-20 4500,200 r0 top
FID4 "Fiducial" Fiducial10-20 4500,3250 r90 bottom
FID5 "Fiducial" Fiducial10-20 4500,200 r90 bottom
FID6 "Fiducial" Fiducial10-20 450,200 r90 bottom
H1 "NY PMS 440 0025 PH" "NY PMS 440 0025 PH" 200,3250 r0 top locked
H2 "NY PMS 440 0025 PH" "NY PMS 440 0025 PH" 4750,3250 r0 top locked
H3 "NY PMS 440 0025 PH" "NY PMS 440 0025 PH" 200,200 r0 top locked
H4 "NY PMS 440 0025 PH" "NY PMS 440 0025 PH" 4750,200 r0 top locked
H5 "1902C" Keystone_1902C 200,3250 r180 bottom locked
H6 "1902C" Keystone_1902C 4750,3250 r180 bottom locked
H7 "1902C" Keystone_1902C 200,200 r180 bottom locked
H8 "1902C" Keystone_1902C 4750,200 r180 bottom locked
J51 "Header_3x1_Launchpad" CONN_PEC03SAAN 1250,1100 r90 top
J52 "Header_3x1_Launchpad" CONN_PEC03SAAN 1400,700 r90 top
J53 "Header_2x1" CONN_PEC02SAAN 1600,900 r90 top
L1 "XAL1580-202MEB" XAL1580 2425,2300 r0 top locked
L2 "XAL1350-222MEB" XAL1350 2425,2300 r0 top locked
L3 "IHLP6767GZER1R0M11" IHLP-6767GZ-11 2425,2350 r0 top locked
L4 "XAL1010-102MEB" XAL1010 2425,2250 r0 top locked
L11 "XAL5030-601MEB" XAL5030 960,2740 r90 top
L22 "XAL5030-601MEB" XAL5030 1310,2660 r0 top
LBL1 "THT-14-423-10" Label_650x200 190,850 r90 top
Logo1 "FCC disclaimer" FCC_disclaimer 2350,3380 r0 top
Logo2 "WEEE logo" WEEE_Minimum 170,1490 r0 top
NT1 "Net-Tie" Net-Tie_10mil 1600,2650 r90 top net-tie
NT2 "Net-Tie" Net-Tie_10mil 1600,2580.65 r270 top net-tie
NT3 "Net-Tie" Net-Tie_10mil 4345,2145 r270 top net-tie
NT8 "Net-Tie" Net-Tie_10mil 2280,1519.35 r90 top net-tie
NT88 "Net-Tie" Net-Tie_10mil 2280,1440.65 r270 top net-tie
Q1 "BUK9Y6R0-60E,115" LFPAK56 1845,2315 r90 top
Q2 "BUK9Y6R0-60E,115" LFPAK56 1845,2100 r90 top
Q3 "BUK9Y6R0-60E,115" LFPAK56 2135,1835 r0 top
Q5 "BUK9Y6R0-60E,115" LFPAK56 3007.28,2315 r270 top
Q6 "BUK9Y6R0-60E,115" LFPAK56 3007.28,2100 r270 top
Q7 "BUK9Y6R0-60E,115" LFPAK56 2760,1835 r0 top
Q8 "BUK9Y6R0-60E,115" LFPAK56 2550,1835 r0 top
R1 "PML100HZPJV1L5" 2512_WIDE 1600,2620 r270 top
R8 "FCSL64R002GER" 2512_WIDE 2280,1480 r90 top
R11 "Resistor" 0603L 1925,2330 r270 bottom
R12 "Resistor" 0603L 1925,2230 r90 bottom
R13 "Resistor" 0603L 2235.79,1790 r0 bottom
R15 "Resistor" 0603L 2935,2185.49 r270 bottom
R16 "Resistor" 0603L 2935,2080 r90 bottom
R17 "Resistor" 0603L 2780,1760 r180 bottom
R18 "Resistor" 0603L 2680,1760 r0 bottom
R19 "CRCW12062R20JNEA" 1206 2315,1875 r90 top
R20 "CRCW12062R20JNEA" 1206 3075,2485 r0 top
R51 "CRCW0603200KFKEA" 0603 1345,1170 r90 top
R52 "CRCW060364K9FKEA" 0603 1345,1036.5 r90 top
R53 "Resistor" 0603L 1490,670 r90 top
R54 "CRCW0603402RFKEA" 0603 2535,895 r90 top
R55 "CRCW0603200KFKEA" 0603 2535,775 r90 top
R56 "CRCW06036K49FKEA" 0603 2535,653.5 r90 top
R57 "CRCW060327R0JNEA" 0603 2690,620 r180 top
R58 "CRCW060314K7FKEA" 0603 2690,685 r0 top
R59 "CRCW06031K00FKEA" 0603 2815,685 r0 top
R60 "CRCW06031K00FKEA" 0603 2940,685 r0 top
R61 "Resistor" 0603L 3055,740 r0 top
R62 "CRCW06032K61FKEA" 0603 3475,605 r270 top
R63 "Resistor" 0603 1915,810 r180 top
R64 "Resistor" 0603L 2450,860 r180 top
R65 "Resistor" 0603L 1935,785 r180 bottom
R66 "Resistor" 0603 2335,1255 r90 top
R67 "Resistor" 0603 2250,615 r180 top
R68 "CRCW060320K0FKEA" 0603 2180,855 r270 bottom
R69 "Resistor" 0603_HV 2395,1290 r270 top
R70 "Resistor" 0603_HV 2455,1290 r270 top
R71 "Resistor" 0603L 2450,680 r90 top
R72 "Resistor" 0603L 2400,680 r90 top
R73 "Resistor" 0603L 1975,1260 r180 top
R74 "Resistor" 0603L 2185,1265 r0 top
R75 "CRCW06032K61FKEA" 0603 820,1258.7 r90 top
T1 "CB35-36-CY" CB35-36-CY 350,2750 r0 top
T2 "CB35-36-CY" CB35-36-CY 350,2150 r0 top
T3 "CB35-36-CY" CB35-36-CY 4600,2200 r180 top
T4 "CB35-36-CY" CB35-36-CY 4600,1600 r180 top
TP1 "5005" Keystone5005 450,3250 r0 top
TP2 "5006" Keystone5006 130,1790 r0 top
TP5 "5005" Keystone5005 4720,2490 r0 top
TP6 "5006" Keystone5006 4720,1305 r0 top
TP7 "5016" Testpoint_Keystone_Compact 1750,3025 r0 top
TP8 "5016" Testpoint_Keystone_Compact 3550,1580 r0 top
TP51 "5007" Keystone5007 1550,1250 r0 top
TP52 "5000" Keystone5000 2675,1075 r90 top
TP53 "5003" Keystone5003 2675,850 r90 top
TP54 "5001" Keystone5001 2875,1075 r90 top
TP55 "5000" Keystone5000 700,1400 r90 top
TP56 "5000" Keystone5000 1775,1250 r90 top
TP57 "5007" Keystone5007 3200,250 r0 top
TP58 "5001" Keystone5001 950,1400 r90 top
TP61 "5000" Keystone5000 3075,850 r90 top
TP62 "5001" Keystone5001 3075,1075 r90 top
TP70 "5003" Keystone5003 2875,850 r90 top
TP71 "5016" Testpoint_Keystone_Compact 2829.68,369.69 r0 top
TP72 "5000" Keystone5000 3200,465 r90 top
U1 "LM5176PWPR" PWP0028C_N 2180,980 r90 top
U2 "TL432BQDBZRQ1" DBZ0003A_N 3370,620 r90 top
U3 "SN74LV1T04DBVR" DBV0005A_N 3080,630 r270 top
ZZ1 "This Assembly Note is for PCB labels only" AssemblyNoteLabel 185,3938 r0 top
ZZ2 "These assemblies are ESD sensitive, ESD precautions shall be observed." AssemblyNote 185,3829.11 r0 top
ZZ3 "These assemblies must be clean and free from flux and all contaminants. Use of no clean flux is not acceptable." AssemblyNote 185,3740.56 r0 top
ZZ4 "These assemblies must comply with workmanship standards IPC-A-610 Class 2, unless otherwise specified." AssemblyNote 185,3652 r0 top

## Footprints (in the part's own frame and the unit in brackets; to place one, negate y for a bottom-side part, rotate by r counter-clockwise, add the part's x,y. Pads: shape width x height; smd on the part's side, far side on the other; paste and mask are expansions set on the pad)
0603 [mm] "0603 from SM-752 data"
  rect 1x0.95 smd: 1(-0.8,0) 2(0.8,0)
  silkscreen extent -1.52,-0.69 1.52,0.69, body extent -0.87,-0.47 0.87,0.47, height 1
0603_HV [mil] "Ernesto recommended land pattern.  26 mil between pads."
  rect 30x30 smd: 1(-28,0) 2(28,0)
  silkscreen extent -52,-24 52,24, body extent -34,-19 34,19, height 39
0603L [mm] "0603 from SM-752 data"
  rect 0.8x0.85 smd: 1(-0.7,0) 2(0.7,0)
  silkscreen extent -0.07,-0.33 0.07,0.33, body extent -0.87,-0.47 0.87,0.47, height 1
0805_HV [mil] "0805 with 30mil clearance between pads"
  rect 50x63 smd: 1(-40,0) 2(40,0)
  silkscreen extent -74,-40 74,40, body extent -43,-29 43,29, height 57
1206 [mm] "1206 from SM-752 data"
  rect 1.3x1.85 smd: 1(-1.45,0) 2(1.45,0)
  silkscreen extent -2.4,-1.21 2.4,1.21, body extent -1.7,-0.9 1.7,0.9, height 1.35
1210_270 [mm] "1210"
  rect 1.3x2.7 smd: 1(-1.45,0) 2(1.45,0)
  silkscreen extent -2.32,-1.57 2.32,1.57, body extent -1.7,-1.35 1.7,1.35, height 2.7
2512_WIDE [mm] "Ohmite recommended land pattern"
  rect 1x6.6 smd: 1(-1.6,0) 2(1.6,0)
  silkscreen extent -0.82,-3.32 0.82,3.35, body extent -1.65,-3.25 1.65,3.25, height 0.7
AssemblyNote [mil] "Assembly Note"
AssemblyNoteLabel [mil] "Assembly Note for PCB Labels"
CB35-36-CY [mil] "Terminal 50A Lug"
  rect 550x380 hole 188 copper offset -45,0 paste-190: 1(0,0)
  body extent -960,-189 230,191, height 614
CONN_PEC02SAAN [mm] "SULLINS"
  rrect7% 1.5x1.5 hole 1.016: 1(-1.27,0)
  round 1.5 hole 1.016: 2(1.27,0)
  silkscreen extent -2.54,-1.52 2.54,1.27, body extent -2.54,-1.27 2.54,1.27, height 8.38
CONN_PEC03SAAN [mm] "SULLINS"
  rect 1.5x1.5 hole 1.016: 1(-2.54,0)
  round 1.5 hole 1.016: 2(0,0) 3(2.54,0)
  silkscreen extent -4.72,-1.27 3.81,1.27, body extent -3.84,-1.3 3.84,1.3, height 8.38
DBV0005A_N [mm] "SOT23, 5-Leads, Body 2.9x1.6mm, Pitch 0.95mm, Lead Span 2.8mm, IPC Medium Density"
  rrect17% 1x0.6 smd: 1(-1.375,0.95) 2(-1.375,0) 3(-1.375,-0.95) 4(1.375,-0.95) 5(1.375,0.95)
  silkscreen extent -1.63,-1.55 0.38,1.55, body extent -1.42,-1.46 1.42,1.46, height 1.09
DBZ0003A_N [mm] "SOT23, 3-Leads, Body 2.9x1.3mm, Pitch 0.95mm, Lead Span 2.4mm, IPC Medium Density"
  rrect17% 1x0.6 smd: 1(-1.2,0.95) 2(-1.2,-0.95) 3(1.2,0)
  silkscreen extent 0.2,-1.5 0.7,1.5, body extent -1.26,-1.46 1.26,1.46, height 0.98
FCC_disclaimer [mil]
Fiducial10-20 [mm]
  round 1 smd mask+0.5: 1(0,0)
  Top Layer keep-out circle w1.178: c0,0 r0.5
IHLP-6767GZ-11 [mil] "Vishay Dale"
  rrect3% 150.5x485 smd: 1(-319.75,0) 2(319.75,0)
  silkscreen extent -343,-339 343,339, body extent -338,-338 338,338, height 272
Keystone5000 [mil] "For Keystone 500x miniature loop terminals"
  round 80 hole 40: 1(0,0)
  silkscreen extent -52,-52 52,52, body extent -49,-49 49,49, height 182
Keystone5001 [mil] "For Keystone 500x miniature loop terminals"
  round 80 hole 40: 1(0,0)
  silkscreen extent -52,-52 52,52, body extent -49,-49 49,49, height 182
Keystone5003 [mil] "For Keystone 500x miniature loop terminals"
  round 80 hole 40: 1(0,0)
  silkscreen extent -52,-52 52,52, body extent -49,-49 49,49, height 182
Keystone5005 [mil] "Keystone Compact loops"
  round 87 hole 63: 1(0,0)
  silkscreen extent -70,-70 70,70, body extent -63,-63 62,63, height 225
Keystone5006 [mil] "Keystone Compact loops"
  round 87 hole 63: 1(0,0)
  silkscreen extent -70,-70 70,70, body extent -63,-63 62,63, height 225
Keystone5007 [mil] "Keystone Compact loops"
  round 87 hole 63: 1(0,0)
  silkscreen extent -70,-70 70,70, body extent -63,-63 62,63, height 225
Keystone_1902C [mil] "Hex Standoff, 4-40 threaded, nylon"
  round 1 on Mech4: 0(0,0)
  body extent -145,-126 146,126, height 501
Label_650x200 [mil] "Thermal Transfer Label"
  round 1 on Mech13: 0(0,0)
  silkscreen extent -325,-100 325,100, body extent -325,-100 325,100, height 1
LED_LTST-C190_G [mm] "Lite-On"
  rect 0.8x0.8 smd: 1(-0.75,0) 2(0.75,0)
  silkscreen extent 1.37,-0.5 1.75,0.5, body extent -0.85,-0.45 0.85,0.45, height 0.9
LFPAK56 [mm] "NXP Semiconductor"
  rect 0.7x1.15 smd paste-0.05: 1(-1.905,-2.725) 2(-0.635,-2.725) 3(0.635,-2.725) 4(1.905,-2.725)
  rect 4.2x2.2 smd paste-1.52: 5(0,0)
  Top Layer region: -2.1,0.65 2.1,0.65 2.1,2 -2.1,2
  Top Layer region: -2.1,1.8 -2.1,2 -2.35,2 -2.35,3.5 2.35,3.5 2.35,2 2.1,2 2.1,1.8
  silkscreen extent -2.5,-3.3 -2.5,-1.8, body extent -2.43,-3.14 2.47,3.29, height 1.18
Net-Tie_10mil [mil] "10mil net tie, no solder mask opening, no solder paste"
  rect 10x10 smd paste-5 mask-5: 1(-10,0) 2(10,0)
  Top Layer region: -6,5 6,5 6,-5 -6,-5
"NY PMS 440 0025 PH" [mm] "4-40 nylon screw and mounting hole"
  round 8 hole 3.2: 1(0,0)
  body extent -3.3,-3.3 3.3,3.3, height 2.69
PWP0028C_N [mm] "TSOP, 28-Leads, Body 9.7x4.4mm, Pitch 0.65mm, Exposed Pad, IPC Medium Density"
  rrect22% 1.4x0.45 smd: 1(-2.95,4.225) 2(-2.95,3.575) 3(-2.95,2.925) 4(-2.95,2.275) 5(-2.95,1.625) 6(-2.95,0.975) 7(-2.95,0.325) 8(-2.95,-0.325) 9(-2.95,-0.975) 10(-2.95,-1.625) 11(-2.95,-2.275) 12(-2.95,-2.925) 13(-2.95,-3.575) 14(-2.95,-4.225) 15(2.95,-4.225) 16(2.95,-3.575) 17(2.95,-2.925) 18(2.95,-2.275) 19(2.95,-1.625) 20(2.95,-0.975) 21(2.95,-0.325) 22(2.95,0.325) 23(2.95,0.975) 24(2.95,1.625) 25(2.95,2.275) 26(2.95,2.925) 27(2.95,3.575) 28(2.95,4.225)
  rrect3% 3.4x9.7 smd paste-1.7 mask-1.7: 29(0,0)
  rrect3% 3.1x5.18 on Top Paste: 29(0,0)
  rrect3% 3.1x5.18 on Top Solder: 29(0,0)
  silkscreen extent -3.5,-4.9 2,4.9, body extent -3.2,-4.85 3.2,4.85, height 1.13
SM_RADIAL_10BMM [mm] "Nichicon 10x10"
  rect 4x2.5 smd: 1(-4,0) 2(4,0)
  silkscreen extent -5.25,-5.25 5.25,5.25, body extent -5.25,-5.25 5.25,5.25, height 10.5
SOD-323 [mm] "NXP recommended land pattern"
  rect 0.6x0.6 smd paste-0.05: 1(-1.1,0) 2(1.1,0)
  silkscreen extent -2.06,-0.86 1.53,0.86, body extent -1.3,-0.67 1.3,0.68, height 1.1
SOD-323F [mm] "NXP recommended land pattern"
  rect 0.6x0.6 smd paste-0.05: 1(-1.1,0) 2(1.1,0)
  silkscreen extent -2.06,-0.86 1.53,0.86, body extent -1.35,-0.67 1.35,0.68, height 0.79
Testpoint_Keystone_Compact [mil] "Compact SMT test point"
  rect 185x135 smd: 1(0,0)
  silkscreen extent -110,-80 110,80, body extent -75,-56 75,56, height 91
WEEE_Minimum [mil] "WEEElie bin"
  silkscreen extent -95,-172 99,104
XAL1010 [mm] "COILCRAFT"
  rect 2.38x11.31 smd: 1(-3.325,0) 2(3.325,0)
  silkscreen extent -2.54,-6 2.54,6, body extent -5.25,-5.9 5.25,5.9, height 10
XAL1350 [mm] "COILCRAFT"
  rect 2.98x12 smd: 1(-4.3,0) 2(4.3,0)
  silkscreen extent -3.17,-7.1 3.17,7.1, body extent -6.6,-7.1 6.6,7.1, height 5.01
XAL1580 [mm] "COILCRAFT"
  rect 3.18x14.36 smd: 1(-5.3,0) 2(5.3,0)
  silkscreen extent -7.4,-7.8 7.4,7.8, body extent -7.7,-7.8 7.7,7.8, height 8
XAL5030 [mil] "Coilcraft XAL5030 12/12/11"
  rect 46x183 smd: 1(-65,0) 2(65,0)
  silkscreen extent -108,-112 108,112, body extent -108,-112 108,112, height 122

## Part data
C1 C4 C30 C37 C38: library part CMP-0007469-4, "CAP, CERM, 0.1 uF, 100 V, +/- 10%, X7R, 0603"
C2 C5 C13 C14 C15 C16 C17 C18 C21 C22 C23 C24 C25 C26 C27 C28: library part CMP-0009226-3, "CAP, CERM, 10 uF, 50 V, +/- 10%, X7R, 1210"
C3 C6 C7 C8: library part CMP-0012596-3, "CAP, Polymer Hybrid, 100 uF, 50 V, +/- 20%, 28 ohm, 10x10 SMD"
C19 C20: library part CMP-0007714-2, "CAP, CERM, 1000 pF, 50 V, +/- 10%, X7R, 0805"
C29 C39 C40: library part CMP-0008350-2, "CAP, CERM, 1 uF, 50 V, +/- 10%, X7R, 0805"
C31 C32 C33 C34 C35 C36: library part CMP-0012606-3, "CAP, Polymer Hybrid, 270 uF, 35 V, +/- 20%, 20 ohm, 10x10 SMD"
C51: library part CMP-0007350-5, "CAP, CERM, 1 uF, 50 V, +/- 10%, X5R, 0603"
C52: library part CMP-0008334-2, "CAP, CERM, 4.7 uF, 16 V, +/- 10%, X7R, 0805"
C53 C54: library part CMP-0007415-4, "CAP, CERM, 0.22 uF, 25 V, +/- 10%, X7R, 0603"
C55 C60 C61: library part CMP-0007093-5, "CAP, CERM, 0.15 uF, 50 V, +/- 10%, X7R, AEC-Q200 Grade 1, 0603"
C56 C57 C63 C64: library part CMP-0007237-4, "CAP, CERM, 100 pF, 100 V, +/- 5%, C0G/NP0, 0603"
C58: library part CMP-0006901-4, "CAP, CERM, 0.022 uF, 50 V, +/- 10%, X7R, 0603"
C59: library part CMP-0007410-5, "CAP, CERM, 0.015 uF, 25 V, +/- 10%, X7R, 0603"
C62: library part CMP-0008012-2, "CAP, CERM, 10 uF, 16 V, +/- 10%, X7S, AEC-Q200 Grade 1, 0805"
C65: library part CMP-0007402-4, "CAP, CERM, 1000 pF, 25 V, +/- 10%, X7R, 0603"
C66: library part CMP-0007393-4, "CAP, CERM, 0.33 uF, 16 V, +/- 10%, X7R, 0603"
C67: library part CMP-0007398-4, "CAP, CERM, 0.47 uF, 16 V, +/- 10%, X7R, 0603"
C68: library part CMP-0007171-4, "CAP, CERM, 100 pF, 50 V, +/- 5%, C0G/NP0, 0603"
C69: library part CMP-0007220-4, "CAP, CERM, 47 pF, 50 V, +/- 5%, C0G/NP0, 0603"
D51 D52: library part CMP-0029006-1, "Diode, Ultrafast, 100 V, 0.25 A, SOD-323"
D53: library part CMP-0077011-1, "Diode, Schottky, 60 V, 1 A, SOD-323F"
D75: library part CMP-0002840-1, "LED, Green, SMD"
FID1 FID2 FID3 FID4 FID5 FID6: library part CMP-0077181-1, "Fiducial mark.  There is nothing to buy or mount."
H1 H2 H3 H4: library part CMP-0003617-1, "Machine Screw, Round, #4-40 x 1/4, Nylon, Philips panhead"
H5 H6 H7 H8: library part CMP-0003610-1, "Standoff, Hex, 0.5\"L #4-40 Nylon"
J51 J52: library part CMP-0002338-1, "Header, 100mil, 3x1, Tin, TH"
J53: library part CMP-0002337-1, "Header, 100mil, 2x1, Tin, TH"
L1: library part CMP-0060976-1, "Inductor, Shielded, Composite, 2 uH, 39.9 A, 0.001909 ohm, SMD"
L2: library part CMP-0060967-1, "Inductor, Shielded, Composite, 2.2 uH, 24 A, 0.0042 ohm, SMD"
L3: library part CMP-0063528-2, "Inductor, Shielded, Powdered Iron, 1 uH, 32 A, 0.00127 ohm, SMD"
L4: library part CMP-0060943-1, "Inductor, Shielded, Composite, 1 uH, 43.5 A, 0.001 ohm, SMD"
L11 L22: library part CMP-0061005-2, "Inductor, Shielded, Composite, 600 nH, 17.7 A, 0.00411 ohm, AEC-Q200 Grade 1, SMD"
LBL1: library part CMP-0003625-1, "Thermal Transfer Printable Labels, 0.650\" W x 0.200\" H - 10,000 per roll"
Logo1: library part CMP-0074847-1, "FCC_disclaimer"
Logo2: library part CMP-0074769-1
NT1 NT2 NT3 NT8 NT88: library part CMP-0078142-2, "Single point connection between nets."
Q1 Q2 Q3 Q5 Q6 Q7 Q8: library part CMP-0000808-2, "MOSFET, N-CH, 60 V, 100 A, AEC-Q101, SOT669"
R1: library part CMP-0084409-1, "RES, 0.0015, 5%, 2 W, 2512 WIDE"
R8: library part CMP-0015353-2, "RES, 0.002, 2%, 2 W, 2512 WIDE"
R11 R12 R13 R15 R16 R17 R18 R64 R65 R73 R74: library part CMP-0025885-5, "RES, 0, 5%, 0.1 W, 0603"
R19 R20: library part CMP-0018649-3, "RES, 2.2, 5%, 0.25 W, AEC-Q200 Grade 0, 1206"
R51 R55: library part CMP-0022200-4, "RES, 200 k, 1%, 0.1 W, AEC-Q200 Grade 0, 0603"
R52: library part CMP-0022544-4, "RES, 64.9 k, 1%, 0.1 W, AEC-Q200 Grade 0, 0603"
R53 R61: library part CMP-0023322-5, "RES, 93.1 k, 1%, 0.1 W, 0603"
R54: library part CMP-0022409-5, "RES, 402, 1%, 0.1 W, AEC-Q200 Grade 0, 0603"
R56: library part CMP-0022561-4, "RES, 6.49 k, 1%, 0.1 W, AEC-Q200 Grade 0, 0603"
R57: library part CMP-0025767-4, "RES, 27, 5%, 0.1 W, AEC-Q200 Grade 0, 0603"
R58: library part CMP-0022056-4, "RES, 14.7 k, 1%, 0.1 W, AEC-Q200 Grade 0, 0603"
R59 R60: library part CMP-0022109-5, "RES, 1.00 k, 1%, 0.1 W, AEC-Q200 Grade 0, 0603"
R62 R75: library part CMP-0022279-4, "RES, 2.61 k, 1%, 0.1 W, AEC-Q200 Grade 0, 0603"
R63: library part CMP-0022751-4, "RES, 10.0, 1%, 0.1 W, 0603"
R66: library part CMP-0022746-5, "RES, 10.0 k, 1%, 0.1 W, 0603"
R67: library part CMP-0022509-4, "RES, 5.11 k, 1%, 0.1 W, AEC-Q200 Grade 0, 0603"
R68: library part CMP-0022204-4, "RES, 20.0 k, 1%, 0.1 W, AEC-Q200 Grade 0, 0603"
R69 R70 R71 R72: library part CMP-0022736-4, "RES, 100, 1%, 0.1 W, 0603"
T1 T2 T3 T4: library part CMP-0055442-1, "Terminal 50A Lug"
TP1 TP5: library part CMP-0055142-1, "Test Point, Compact, Red, TH"
TP2 TP6: library part CMP-0055143-1, "Test Point, Compact, Black, TH"
TP7 TP8 TP71: library part CMP-0055153-1, "Test Point, Compact, SMT"
TP51 TP57: library part CMP-0055144-1, "Test Point, Compact, White, TH"
TP52 TP55 TP56 TP61 TP72: library part CMP-0055137-1, "Test Point, Miniature, Red, TH"
TP53 TP70: library part CMP-0055140-1, "Test Point, Miniature, Orange, TH"
TP54 TP58 TP62: library part CMP-0055138-1, "Test Point, Miniature, Black, TH"
U1: library part CMP-0013685-4, "55 V Wide VIN Synchronous 4-Switch Buck-Boost Controller, PWP0028C (TSSOP-28)"
U2: library part CMP-0032978-1, "Automotive Catalog Adjustable Precision Shunt Regulator, 34 ppm / degC, 100 mA, -40 to 125 degC, 3-pin SOT-23 (DBZ), Green (RoHS & no Sb/Br)"
U3: library part CMP-0051667-2, "Single Power Supply INVERTER Gate logic level shifter, DBV0005A (SOT-23-5)"
ZZ1: library part CMP-0003616-3
ZZ2: library part CMP-0077236-1
ZZ3: library part CMP-0077237-1
ZZ4: library part CMP-0077238-1

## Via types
v1: diameter 20, hole 10, Top Layer to Bottom Layer, tented both sides, 820 vias
v2: diameter 32, hole 16, Top Layer to Bottom Layer, 112 vias
v3: diameter 19.68, hole 7.87, Top Layer to Bottom Layer, tented both sides, 12 vias
v4: diameter 19.68, hole 7.87, Top Layer to Bottom Layer, 9 vias

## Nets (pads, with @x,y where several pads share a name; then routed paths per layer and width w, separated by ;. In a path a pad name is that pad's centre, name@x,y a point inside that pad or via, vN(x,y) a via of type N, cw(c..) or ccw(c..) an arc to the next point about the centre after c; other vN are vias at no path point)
2v5: C62.1 R62.2 TP72.1 U2.1 U2.2 U3.5
CS: NT8.1 R69.1 | length 380.7
  Top Layer w10: v1(2280,1495) NT8.1@2280,1509.35 ; R69.1@2395,1318 2410,1333 v1(2410,1350)
  Signal Layer 2 w10: v1(2280,1495) 2275,1490 2250,1490 2235,1475 2235,1425 2255,1405 2380,1405 2415,1370 2415,1355 v1(2410,1350)
CSG: NT88.1 R70.1 | length 346.6
  Top Layer w10: NT88.1@2280,1450.65 v1(2280,1465) ; v1(2440,1350) 2440,1333 R70.1@2455,1318
  Signal Layer 2 w10: v1(2280,1465) 2275,1470 2260,1470 2255,1465 2255,1435 2265,1425 2390,1425 2435,1380 2435,1355 v1(2440,1350)
DITHER: C58.1 J53.2 U1.5 | length 795.8
  Top Layer w10: C58.1@2050,737.56 2060,747.56 2060,760 2090,790 v1(2105,790) 2116.02,801.02 U1.5@2116.02,863.86
  Bottom Layer w10: J53.2@1600,950 1835,715 2030,715 v1(2105,790)
EN: C63.2 J51.2 R51.1 R52.2 U1.1 | length 1030.7
  Top Layer w10: J51.2@1250,1100 1282.01,1067.99 R52.2@1345,1067.99 ; R51.1@1345,1138.5 R52.2@1345,1067.99 ; U1.1@2013.66,863.86 1947.64,863.86 C63.2@1946.5,865 1946.5,1033.5 1912.01,1067.99 R52.2@1345,1067.99
GND: C1.2 C2.2 C3.2 C4.2 C5.2 C6.2 C7.2 C8.2 C13.2 C14.2 C15.2 C16.2 C17.2 C18.2 C21.2 C22.2 C23.2 C24.2 C25.2 C26.2 C27.2 C28.2 C29.2 C30.2 C31.2 C32.2 C33.2 C34.2 C35.2 C36.2 C51.2 C52.1 C55.2 C56.1 C58.2 C60.2 C61.2 C62.2 C63.1 C64.1 C65.2 C67.2 C68.2 D75.2 J51.1 J52.1 J53.1 NT88.2 R8.1 R52.1 R53.1 R57.1 R61.1 R67.1 R68.1 T2.1 T4.1 TP2.1 TP6.1 TP7.1 TP8.1 TP54.1 TP58.1 TP62.1 TP71.1 U1.10 U1.22 U1.29@2180,980 U2.3 U3.3 | length 1049.8
  Top Layer w15: U1.22@2167.2,1096.14 2167.2,992.8 v4(2180,980) v4(2231.18,928.82) 2243.98,916.02 U1.10@2243.98,863.86
  Top Layer w20: D75.2@820,1099.17 v1(850,1099.17) ; C63.1@1883.5,865 v1(1883.5,898.5) ; v1(1995,645) C64.1@1995,678.5 ; v1(2050,648.94) C58.2@2050,682.44 ; v1(2105,645) C68.2@2105,678.5 ; v1(2160,648.94) C67.2@2160,682.44 ; C65.2@2280,678.5 v1(2280,645) 2280,616.5 R67.1@2281.5,615 v1(2315,615) ; v1(2340,645) C56.1@2340,678.5 ; v1(2721.5,586.5) R57.1@2721.5,620 ; v1(2780,520) C60.2@2780,553.5 ; v1(2850,520) C61.2@2850,553.5 ; v1(3027.44,770) R61.1@3027.44,740 3027.44,707.56 3042.6,692.4 U3.3@3042.6,684.13 ; U2.3@3370,667.24 v1(3370,700)
  Top Layer w30: J51.1@1250,1000 1255,1005 R52.1@1345,1005
  Bottom Layer w20: C51.2@1990,911.5 2007.32,928.82 v3(2022.52,928.82) ; v4(2128.82,1031.18) 2145,1047.36 C55.2@2145,1077.01 ; R68.1@2180,886.5 v4(2180,928.82)
  other v1: 508,66 708,66 908,66 1108,66 1308,66 1508,66 1708,66 1908,66 2108,66 2308,66 2508,66 2708,66 2908,66 3108,66 3308,66 3508,66 3708,66 3908,66 4108,66 4308,66 4508,66 408,266 608,266 808,266 3608,266 3808,266 4008,266 4208,266 4408,266 2724.68,279.69 2754.68,279.69 2784.68,279.69 2814.68,279.69 2844.68,279.69 2874.68,279.69 2904.68,279.69 2934.68,279.69 2724.68,309.69 2934.68,309.69 2724.68,339.69 2934.68,339.69 2724.68,369.69 2934.68,369.69 2724.68,399.69 2934.68,399.69 2724.68,429.69 2934.68,429.69 2724.68,459.69 2754.68,459.69 2784.68,459.69 2814.68,459.69 2844.68,459.69 2874.68,459.69 2904.68,459.69 2934.68,459.69 108,466 308,466 508,466 708,466 3708,466 3908,466 4108,466 4308,466 4508,466 4708,466 208,666 408,666 608,666 3608,666 3808,666 4008,666 4208,666 4408,666 4608,666 4808,666 3180,695 3210,695 108,866 308,866 508,866 3708,866 3908,866 4108,866 4308,866 4508,866 4708,866 208,1066 408,1066 608,1066 3608,1066 3808,1066 4008,1066 4208,1066 4408,1066 4608,1066 4808,1066 108,1266 308,1266 508,1266 3508,1266 3708,1266 3908,1266 4108,1266 4508,1266 2070,1335 2100,1335 2140,1350 2170,1350 2200,1350 2230,1350 2260,1350 2290,1350 2320,1350 2350,1350 2125,1375 2155,1375 2185,1375 2215,1375 2245,1375 2275,1375 2305,1375 2335,1375 2365,1375 2100,1390 2125,1405 2100,1420 2125,1435 208,1466 408,1466 608,1466 2408,1466 3408,1466 3608,1466 3808,1466 4008,1466 4208,1466 3445,1490 3475,1490 3505,1490 3535,1490 3565,1490 3595,1490 3625,1490 3655,1490 3445,1520 3655,1520 3445,1550 3655,1550 3445,1580 3655,1580 3445,1610 3655,1610 3445,1640 3655,1640 108,1666 308,1666 508,1666 708,1666 908,1666 1108,1666 3708,1666 3908,1666 4108,1666 3445,1670 3475,1670 3505,1670 3535,1670 3565,1670 3595,1670 3625,1670 3655,1670 2885,1755 2915,1755 2990,1755 1915,1760 1990,1760 2885,1785 2915,1785 2990,1785 1915,1790 1990,1790 2885,1815 2915,1815 2990,1815 1915,1820 1990,1820 2885,1845 2915,1845 2990,1845 1915,1850 1990,1850 208,1866 408,1866 608,1866 808,1866 1008,1866 1208,1866 3408,1866 3608,1866 3808,1866 4008,1866 4208,1866 4408,1866 4608,1866 4808,1866 2885,1875 2915,1875 2990,1875 1915,1880 1990,1880 1915,1910 1990,1910 1915,1940 1990,1940 3300,1965 3375,1965 1915,1970 1990,1970 2915,1970 2990,1970 1410,1980 1500,1980 3300,1995 3375,1995 1410,2010 1500,2010 3300,2025 3375,2025 3685,2030 3715,2030 3745,2030 3775,2030 3805,2030 3835,2030 3865,2030 3895,2030 3925,2030 3955,2030 3985,2030 4015,2030 4045,2030 4075,2030 4105,2030 4135,2030 4165,2030 4195,2030 4225,2030 4255,2030 1410,2040 1500,2040 4285,2050 4315,2050 3300,2055 3375,2055 4195,2060 4225,2060 4255,2060 708,2066 908,2066 1108,2066 3508,2066 1410,2070 1500,2070 4285,2080 4315,2080 3300,2085 3375,2085 1410,2100 1500,2100 3300,2115 3375,2115 3685,2120 3715,2120 3745,2120 3775,2120 3805,2120 3835,2120 3865,2120 3895,2120 3925,2120 3955,2120 3985,2120 4015,2120 4045,2120 4075,2120 4105,2120 4135,2120 4165,2120 1410,2130 1500,2130 860,2138.04 890,2138.04 920,2138.04 950,2138.04 980,2138.04 3300,2145 3375,2145 1410,2160 1500,2160 860,2168.04 980,2168.04 3300,2175 3375,2175 1410,2190 1500,2190 860,2198.04 980,2198.04 3300,2205 3375,2205 1410,2220 1500,2220 860,2228.04 980,2228.04 3300,2235 3375,2235 1410,2250 1500,2250 860,2258.04 980,2258.04 3300,2265 3375,2265 608,2266 808,2266 1008,2266 1208,2266 1410,2280 1500,2280 860,2288.04 980,2288.04 1410,2310 860,2318.04 890,2318.04 920,2318.04 950,2318.04 980,2318.04 1410,2340 605,2350 635,2350 665,2350 695,2350 515,2360 545,2360 575,2360 1410,2370 515,2390 545,2390 575,2390 1410,2400 1440,2400 1470,2400 1410,2430 1108,2466 3550,2626.96 3580,2626.96 3610,2626.96 3640,2626.96 3670,2626.96 4010,2626.96 4040,2626.96 4070,2626.96 4100,2626.96 4130,2626.96 3550,2656.96 3670,2656.96 4010,2656.96 4130,2656.96 3808,2666 4808,2666 3550,2686.96 3670,2686.96 4010,2686.96 4130,2686.96 3550,2716.96 3670,2716.96 4010,2716.96 4130,2716.96 3550,2746.96 3670,2746.96 4010,2746.96 4130,2746.96 4676.96,2770 4706.96,2770 4736.96,2770 4766.96,2770 4796.96,2770 4826.96,2770 4856.96,2770 3550,2776.96 3670,2776.96 4010,2776.96 4130,2776.96 4676.96,2800 4856.96,2800 3550,2806.96 3580,2806.96 3610,2806.96 3640,2806.96 3670,2806.96 4010,2806.96 4040,2806.96 4070,2806.96 4100,2806.96 4130,2806.96 4676.96,2830 4856.96,2830 4676.96,2860 4856.96,2860 2908,2866 860,2880 890,2880 920,2880 4676.96,2890 4706.96,2890 4736.96,2890 4766.96,2890 4796.96,2890 4826.96,2890 4856.96,2890 860,2910 890,2910 920,2910 950,2910 1750,2910 1780,2910 1810,2910 1840,2910 1870,2910 1900,2910 1930,2910 1960,2910 1990,2910 1645,2935 1675,2935 1705,2935 1735,2935 1765,2935 1795,2935 1825,2935 1855,2935 1885,2935 1915,2935 1945,2935 1975,2935 860,2940 950,2940 1388,2960 1418,2960 1448,2960 1478,2960 1508,2960 1538,2960 1568,2960 1645,2965 1855,2965 860,2970 950,2970 1388,2990 1568,2990 1645,2995 1855,2995 860,3000 950,3000 1388,3020 1568,3020 1645,3025 1855,3025 860,3030 950,3030 3095,3032 3125,3032 3155,3032 3185,3032 3215,3032 1388,3050 1568,3050 1645,3055 1855,3055 860,3060 890,3060 920,3060 950,3060 3095,3062 3215,3062 1608,3066 2808,3066 3008,3066 4608,3066 4808,3066 1388,3080 1418,3080 1448,3080 1478,3080 1508,3080 1538,3080 1568,3080 1645,3085 1855,3085 3095,3092 3215,3092 1645,3115 1675,3115 1705,3115 1735,3115 1765,3115 1795,3115 1825,3115 1855,3115 3095,3122 3215,3122 3095,3152 3215,3152 3095,3182 3215,3182 2070,3187 2100,3187 2130,3187 2160,3187 2190,3187 2515,3187 2545,3187 2575,3187 2605,3187 2635,3187 3550,3188 3580,3188 3610,3188 3640,3188 3670,3188 4010,3188 4040,3188 4070,3188 4100,3188 4130,3188 3095,3212 3125,3212 3155,3212 3185,3212 3215,3212 2070,3217 2190,3217 2515,3217 2635,3217 3550,3218 3670,3218 4010,3218 4130,3218 2070,3247 2190,3247 2515,3247 2635,3247 3550,3248 3670,3248 4010,3248 4130,3248 908,3266 1108,3266 1308,3266 1508,3266 1708,3266 1908,3266 2308,3266 2708,3266 2908,3266 3108,3266 3308,3266 3508,3266 3708,3266 3908,3266 4308,3266 2070,3277 2190,3277 2515,3277 2635,3277 3550,3278 3670,3278 4010,3278 4130,3278 2070,3307 2190,3307 2515,3307 2635,3307 3550,3308 3670,3308 4010,3308 4130,3308 2070,3337 2190,3337 2515,3337 2635,3337 3550,3338 3670,3338 4010,3338 4130,3338 2070,3367 2100,3367 2130,3367 2160,3367 2190,3367 2515,3367 2545,3367 2575,3367 2605,3367 2635,3367 3550,3368 3580,3368 3610,3368 3640,3368 3670,3368 4010,3368 4040,3368 4070,3368 4100,3368 4130,3368
  other v2: 4395,1440 4440,1440 4760,1440 4805,1440 4850,1440 4895,1440 4395,1485 4805,1485 4850,1485 4895,1485 4850,1530 4895,1530 4850,1575 4895,1575 4850,1620 4895,1620 4850,1665 4895,1665 4395,1710 4805,1710 4850,1710 4895,1710 4395,1755 4440,1755 4760,1755 4805,1755 4850,1755 4895,1755 55,1995 100,1995 145,1995 190,1995 510,1995 555,1995 55,2040 100,2040 145,2040 555,2040 55,2085 100,2085 55,2130 100,2130 55,2175 100,2175 55,2220 100,2220 55,2265 100,2265 145,2265 555,2265 55,2310 100,2310 145,2310 190,2310 510,2310 555,2310
  other v3: 2073.7,928.82 2286.3,928.82 2337.48,928.82 2022.52,980 2073.7,980 2286.3,980 2337.48,980 2022.52,1031.18 2073.7,1031.18 2286.3,1031.18 2337.48,1031.18
  other v4: 2128.82,928.82 2128.82,980 2231.18,980 2180,1031.18 2231.18,1031.18
HO1: R11.2 R12.2 U1.27 | length 2705.8
  Top Layer w10: U1.27@2039.25,1096.14 v1(2039.25,1140)
  Signal Layer 2 w10: v1(2000,2395) 1988,2383 1964.72,2383 1930.72,2349 1487.07,2349 1445,2306.93 1445,1106.72 1516.72,1035 1934.25,1035 v1(2039.25,1140)
  Bottom Layer w10: R12.2@1920,2257.56 1920,2303.45 1950,2303.45 1965,2318.45 1965,2385 1975,2395 v1(2000,2395)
